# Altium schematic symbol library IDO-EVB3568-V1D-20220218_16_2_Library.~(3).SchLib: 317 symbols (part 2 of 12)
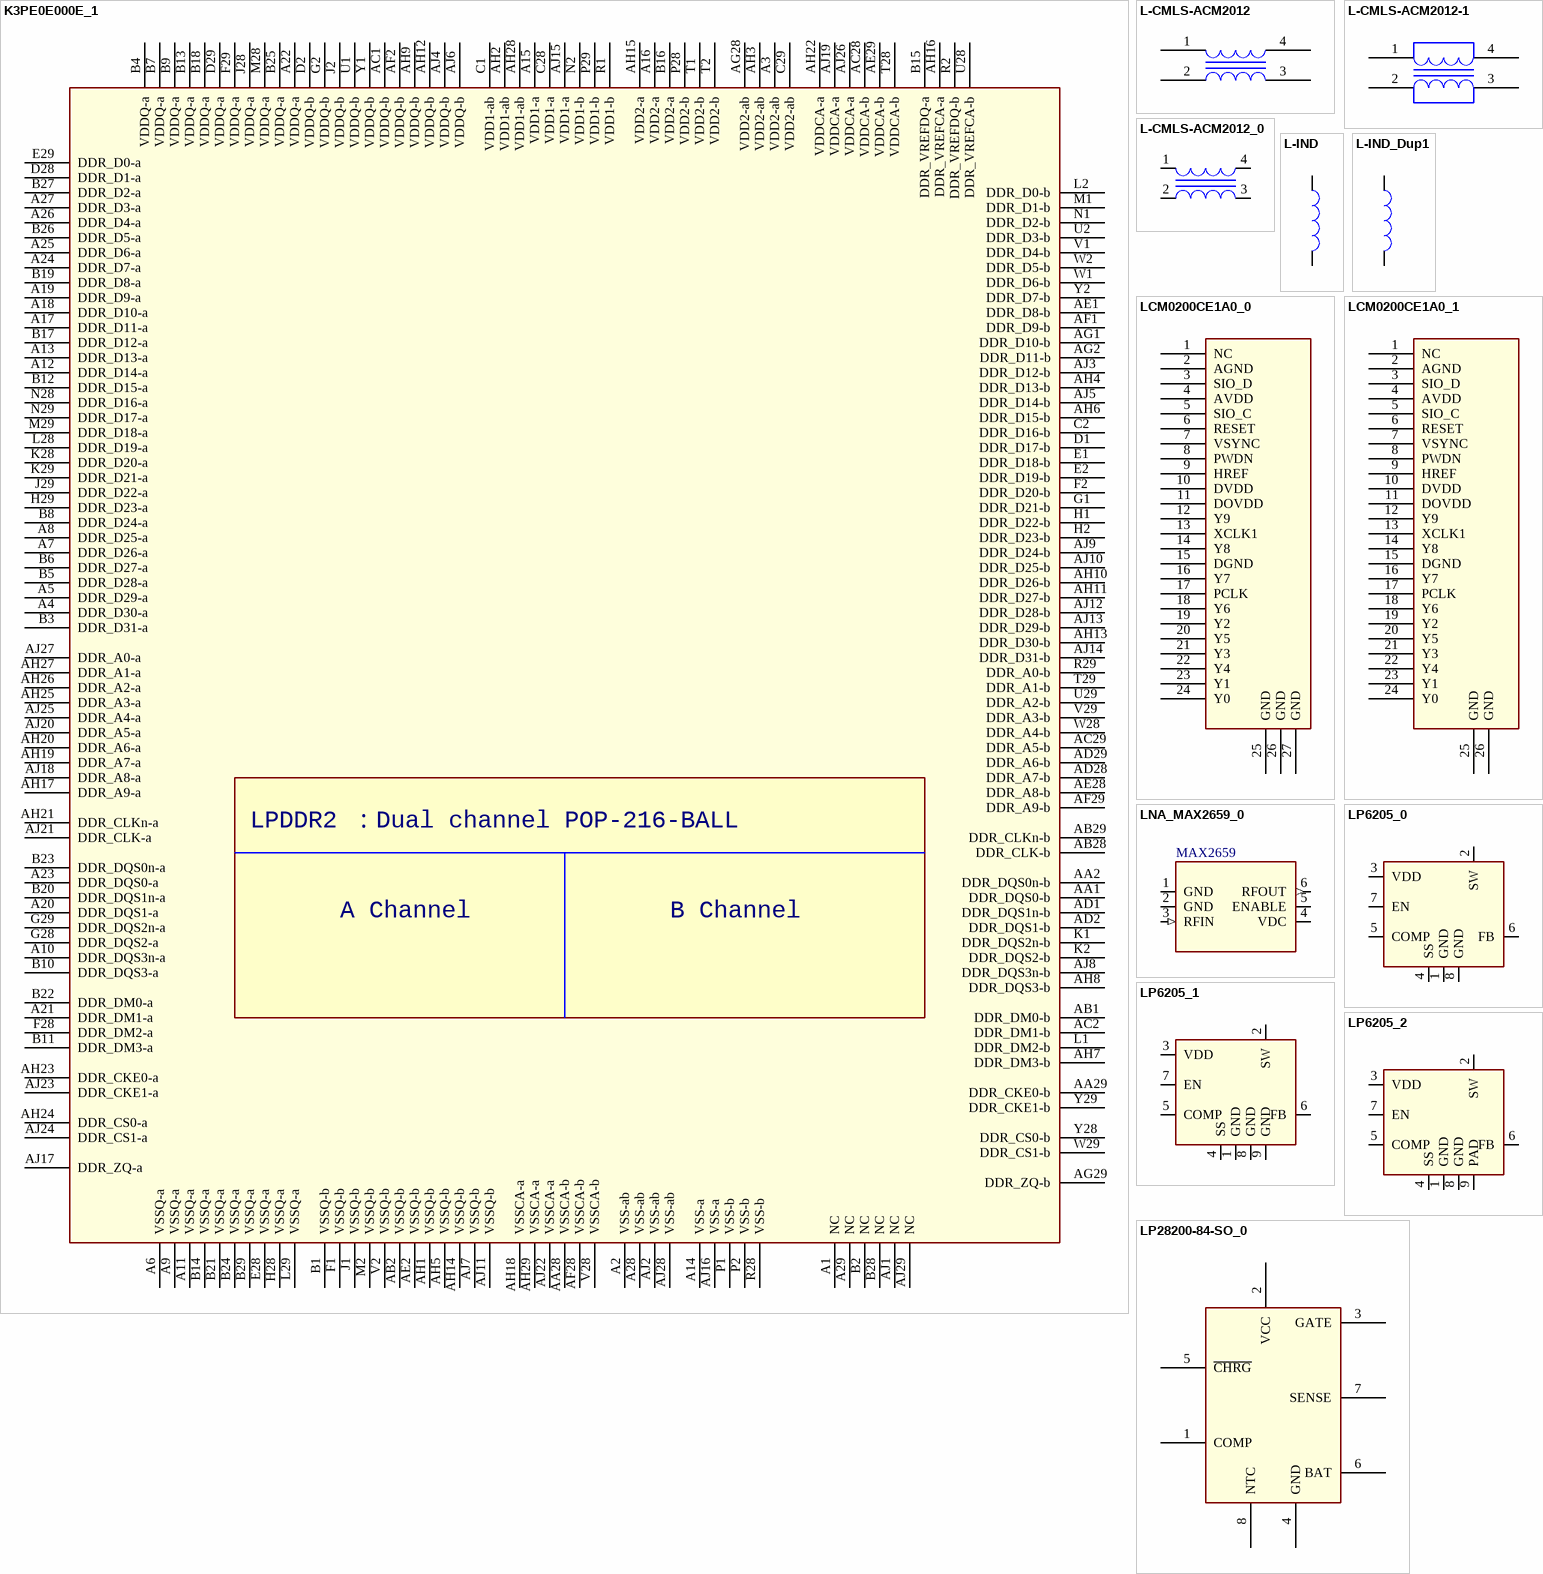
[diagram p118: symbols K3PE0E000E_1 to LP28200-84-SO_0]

## LP6205_1
designator U?
Altium-Right: 80; Altium-Bottom: 70
pins: 1 GND, 2 SW, 3 VDD, 4 SS, 5 COMP, 6 FB, 7 EN, 8 GND, 9 GND

## LP6205_2
designator U?
Altium-Right: 80; Altium-Bottom: 70
pins: 1 GND, 2 SW, 3 VDD, 4 SS, 5 COMP, 6 FB, 7 EN, 8 GND, 9 PAD

## LP28200-84-SO_0
designator U?
Altium-Right: 90; Altium-Bottom: 130
footprint SOP8
pins: 1 COMP, 2 VCC, 3 GATE, 4 GND, 5 ~{CHRG}, 6 BAT, 7 SENSE, 8 NTC

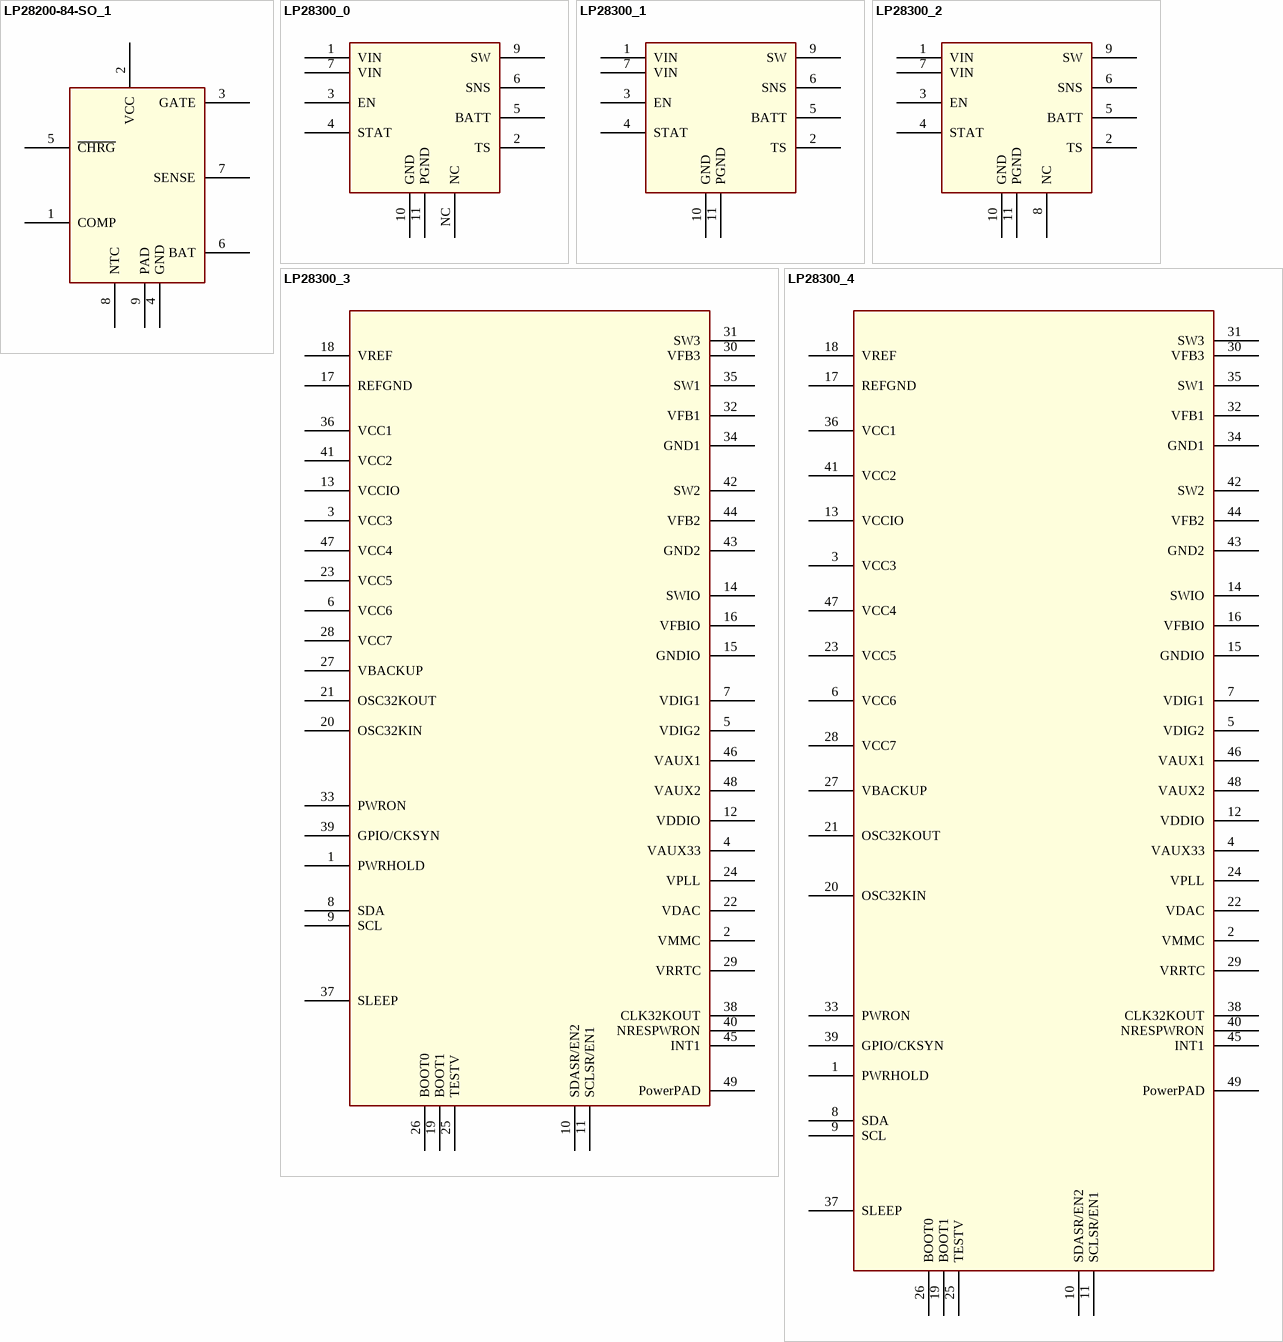
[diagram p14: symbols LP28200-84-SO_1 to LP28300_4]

## LP28200-84-SO_1
designator U?
Altium-Right: 90; Altium-Bottom: 130
footprint SOP8
pins: 1 COMP, 2 VCC, 3 GATE, 4 GND, 5 ~{CHRG}, 6 BAT, 7 SENSE, 8 NTC, 9 PAD

## LP28300_0
designator U?
Altium-Right: 100
footprint TDFN10
pins: 1 VIN, 2 TS, 3 EN, 4 STAT, 5 BATT, 6 SNS, 7 VIN, 9 SW, 10 GND, 11 PGND, NC

## LP28300_1
designator U?
Altium-Right: 100
footprint TDFN10
pins: 1 VIN, 2 TS, 3 EN, 4 STAT, 5 BATT, 6 SNS, 7 VIN, 9 SW, 10 GND, 11 PGND

## LP28300_2
designator U?
Altium-Right: 100
footprint TDFN10
pins: 1 VIN, 2 TS, 3 EN, 4 STAT, 5 BATT, 6 SNS, 7 VIN, 8 NC, 9 SW, 10 GND, 11 PGND

## LP28300_3
designator U?
Altium-Right: 240; Altium-Bottom: 530
footprint TDFN10
pins: 1 PWRHOLD, 2 VMMC, 3 VCC3, 4 VAUX33, 5 VDIG2, 6 VCC6, 7 VDIG1, 8 SDA, 9 SCL, 10 SDASR/EN2, 11 SCLSR/EN1, 12 VDDIO, 13 VCCIO, 14 SWIO, 15 GNDIO, 16 VFBIO, 17 REFGND, 18 VREF, 19 BOOT1, 20 OSC32KIN, 21 OSC32KOUT, 22 VDAC, 23 VCC5, 24 VPLL, 25 TESTV, 26 BOOT0, 27 VBACKUP, 28 VCC7, 29 VRRTC, 30 VFB3, 31 SW3, 32 VFB1, 33 PWRON, 34 GND1, 35 SW1, 36 VCC1, 37 SLEEP, 38 CLK32KOUT, 39 GPIO/CKSYN, 40 NRESPWRON, 41 VCC2, 42 SW2, 43 GND2, 44 VFB2, 45 INT1, 46 VAUX1, 47 VCC4, 48 VAUX2, 49 PowerPAD

## LP28300_4
designator U?
Altium-Right: 240; Altium-Bottom: 640
footprint TDFN10
pins: 1 PWRHOLD, 2 VMMC, 3 VCC3, 4 VAUX33, 5 VDIG2, 6 VCC6, 7 VDIG1, 8 SDA, 9 SCL, 10 SDASR/EN2, 11 SCLSR/EN1, 12 VDDIO, 13 VCCIO, 14 SWIO, 15 GNDIO, 16 VFBIO, 17 REFGND, 18 VREF, 19 BOOT1, 20 OSC32KIN, 21 OSC32KOUT, 22 VDAC, 23 VCC5, 24 VPLL, 25 TESTV, 26 BOOT0, 27 VBACKUP, 28 VCC7, 29 VRRTC, 30 VFB3, 31 SW3, 32 VFB1, 33 PWRON, 34 GND1, 35 SW1, 36 VCC1, 37 SLEEP, 38 CLK32KOUT, 39 GPIO/CKSYN, 40 NRESPWRON, 41 VCC2, 42 SW2, 43 GND2, 44 VFB2, 45 INT1, 46 VAUX1, 47 VCC4, 48 VAUX2, 49 PowerPAD

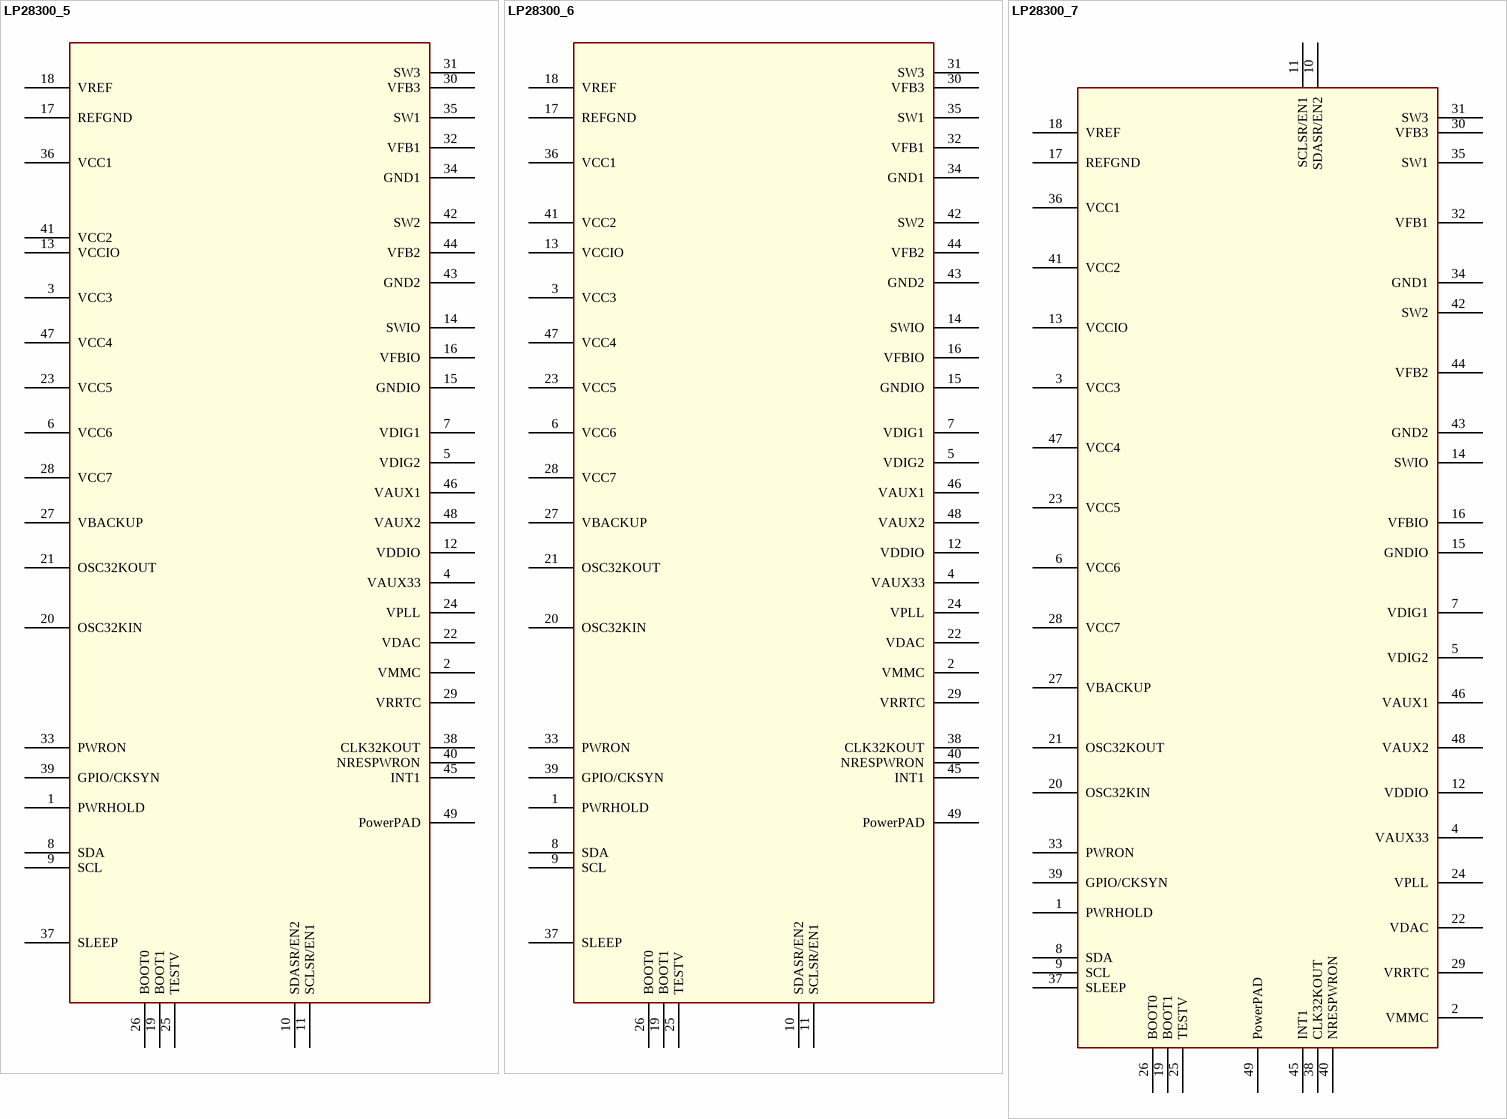
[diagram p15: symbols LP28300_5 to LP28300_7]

## LP28300_5
designator U?
Altium-Right: 240; Altium-Bottom: 640
footprint TDFN10
pins: 1 PWRHOLD, 2 VMMC, 3 VCC3, 4 VAUX33, 5 VDIG2, 6 VCC6, 7 VDIG1, 8 SDA, 9 SCL, 10 SDASR/EN2, 11 SCLSR/EN1, 12 VDDIO, 13 VCCIO, 14 SWIO, 15 GNDIO, 16 VFBIO, 17 REFGND, 18 VREF, 19 BOOT1, 20 OSC32KIN, 21 OSC32KOUT, 22 VDAC, 23 VCC5, 24 VPLL, 25 TESTV, 26 BOOT0, 27 VBACKUP, 28 VCC7, 29 VRRTC, 30 VFB3, 31 SW3, 32 VFB1, 33 PWRON, 34 GND1, 35 SW1, 36 VCC1, 37 SLEEP, 38 CLK32KOUT, 39 GPIO/CKSYN, 40 NRESPWRON, 41 VCC2, 42 SW2, 43 GND2, 44 VFB2, 45 INT1, 46 VAUX1, 47 VCC4, 48 VAUX2, 49 PowerPAD

## LP28300_6
designator U?
Altium-Right: 240; Altium-Bottom: 640
footprint TDFN10
pins: 1 PWRHOLD, 2 VMMC, 3 VCC3, 4 VAUX33, 5 VDIG2, 6 VCC6, 7 VDIG1, 8 SDA, 9 SCL, 10 SDASR/EN2, 11 SCLSR/EN1, 12 VDDIO, 13 VCCIO, 14 SWIO, 15 GNDIO, 16 VFBIO, 17 REFGND, 18 VREF, 19 BOOT1, 20 OSC32KIN, 21 OSC32KOUT, 22 VDAC, 23 VCC5, 24 VPLL, 25 TESTV, 26 BOOT0, 27 VBACKUP, 28 VCC7, 29 VRRTC, 30 VFB3, 31 SW3, 32 VFB1, 33 PWRON, 34 GND1, 35 SW1, 36 VCC1, 37 SLEEP, 38 CLK32KOUT, 39 GPIO/CKSYN, 40 NRESPWRON, 41 VCC2, 42 SW2, 43 GND2, 44 VFB2, 45 INT1, 46 VAUX1, 47 VCC4, 48 VAUX2, 49 PowerPAD

## LP28300_7
designator U?
Altium-Right: 240; Altium-Bottom: 640
footprint TDFN10
pins: 1 PWRHOLD, 2 VMMC, 3 VCC3, 4 VAUX33, 5 VDIG2, 6 VCC6, 7 VDIG1, 8 SDA, 9 SCL, 10 SDASR/EN2, 11 SCLSR/EN1, 12 VDDIO, 13 VCCIO, 14 SWIO, 15 GNDIO, 16 VFBIO, 17 REFGND, 18 VREF, 19 BOOT1, 20 OSC32KIN, 21 OSC32KOUT, 22 VDAC, 23 VCC5, 24 VPLL, 25 TESTV, 26 BOOT0, 27 VBACKUP, 28 VCC7, 29 VRRTC, 30 VFB3, 31 SW3, 32 VFB1, 33 PWRON, 34 GND1, 35 SW1, 36 VCC1, 37 SLEEP, 38 CLK32KOUT, 39 GPIO/CKSYN, 40 NRESPWRON, 41 VCC2, 42 SW2, 43 GND2, 44 VFB2, 45 INT1, 46 VAUX1, 47 VCC4, 48 VAUX2, 49 PowerPAD

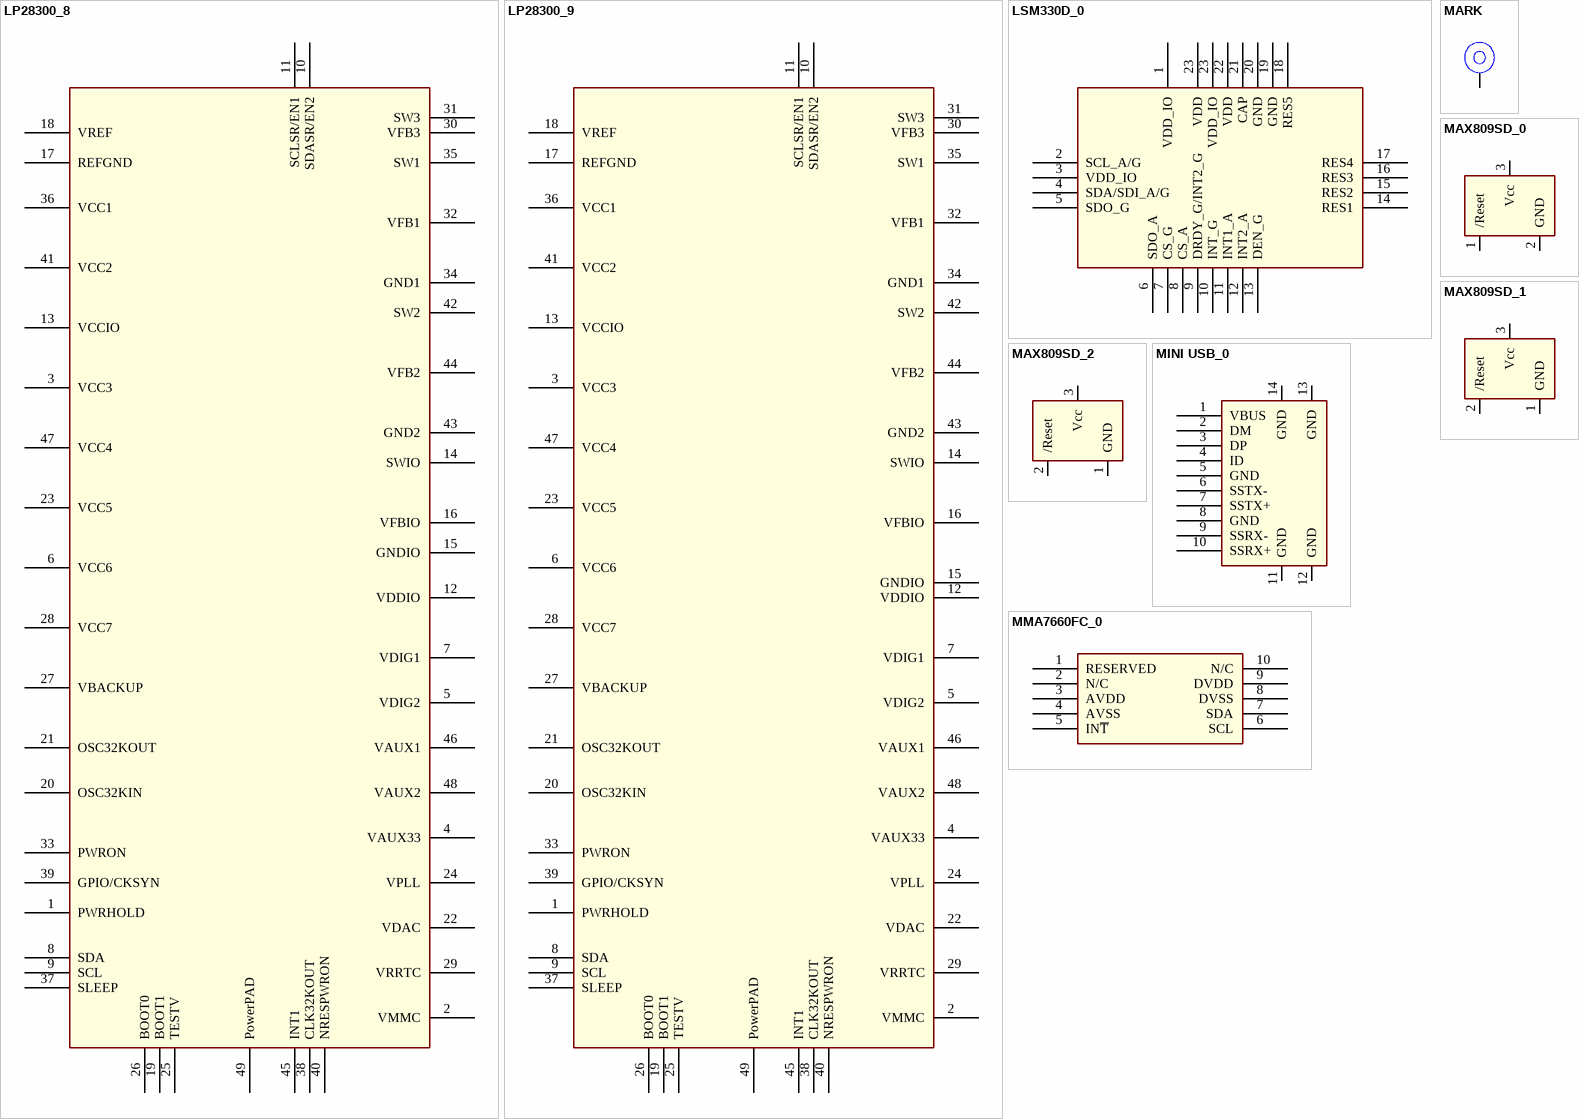
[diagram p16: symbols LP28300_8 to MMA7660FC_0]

## LP28300_8
designator U?
Altium-Right: 240; Altium-Bottom: 640
footprint TDFN10
pins: 1 PWRHOLD, 2 VMMC, 3 VCC3, 4 VAUX33, 5 VDIG2, 6 VCC6, 7 VDIG1, 8 SDA, 9 SCL, 10 SDASR/EN2, 11 SCLSR/EN1, 12 VDDIO, 13 VCCIO, 14 SWIO, 15 GNDIO, 16 VFBIO, 17 REFGND, 18 VREF, 19 BOOT1, 20 OSC32KIN, 21 OSC32KOUT, 22 VDAC, 23 VCC5, 24 VPLL, 25 TESTV, 26 BOOT0, 27 VBACKUP, 28 VCC7, 29 VRRTC, 30 VFB3, 31 SW3, 32 VFB1, 33 PWRON, 34 GND1, 35 SW1, 36 VCC1, 37 SLEEP, 38 CLK32KOUT, 39 GPIO/CKSYN, 40 NRESPWRON, 41 VCC2, 42 SW2, 43 GND2, 44 VFB2, 45 INT1, 46 VAUX1, 47 VCC4, 48 VAUX2, 49 PowerPAD

## LP28300_9
designator U?
Altium-Right: 240; Altium-Bottom: 640
footprint TDFN10
pins: 1 PWRHOLD, 2 VMMC, 3 VCC3, 4 VAUX33, 5 VDIG2, 6 VCC6, 7 VDIG1, 8 SDA, 9 SCL, 10 SDASR/EN2, 11 SCLSR/EN1, 12 VDDIO, 13 VCCIO, 14 SWIO, 15 GNDIO, 16 VFBIO, 17 REFGND, 18 VREF, 19 BOOT1, 20 OSC32KIN, 21 OSC32KOUT, 22 VDAC, 23 VCC5, 24 VPLL, 25 TESTV, 26 BOOT0, 27 VBACKUP, 28 VCC7, 29 VRRTC, 30 VFB3, 31 SW3, 32 VFB1, 33 PWRON, 34 GND1, 35 SW1, 36 VCC1, 37 SLEEP, 38 CLK32KOUT, 39 GPIO/CKSYN, 40 NRESPWRON, 41 VCC2, 42 SW2, 43 GND2, 44 VFB2, 45 INT1, 46 VAUX1, 47 VCC4, 48 VAUX2, 49 PowerPAD

## LSM330D_0
designator U?
Altium-Right: 190; Altium-Bottom: 120
footprint L3G4200D
pins: 1 VDD_IO, 2 SCL_A/G, 3 VDD_IO, 4 SDA/SDI_A/G, 5 SDO_G, 6 SDO_A, 7 CS_G, 8 CS_A, 9 DRDY_G/INT2_G, 10 INT_G, 11 INT1_A, 12 INT2_A, 13 DEN_G, 14 RES1, 15 RES2, 16 RES3, 17 RES4, 18 RES5, 19 GND (power), 20 GND (power), 21 CAP, 22 VDD, 23 VDD, 23 VDD_IO

## MARK
designator M?
Altium-Right: 20
pins: 1

## MAX809SD_0
designator U?
Altium-Right: 60; Altium-Bottom: 40
pins: 1 /Reset, 2 GND, 3 Vcc

## MAX809SD_1
designator U?
Altium-Right: 60; Altium-Bottom: 40
pins: 1 GND, 2 /Reset, 3 Vcc

## MAX809SD_2
designator U?
Altium-Right: 60; Altium-Bottom: 40
pins: 1 GND, 2 /Reset, 3 Vcc

## MINI USB_0
designator U?
Altium-Right: 70; Altium-Bottom: 110
pins: 1 VBUS, 2 DM, 3 DP, 4 ID, 5 GND, 6 SSTX-, 7 SSTX+, 8 GND (power), 9 SSRX-, 10 SSRX+, 11 GND, 12 GND, 13 GND, 14 GND

## MMA7660FC_0
designator U?
Altium-Right: 110; Altium-Bottom: 60
pins: 1 RESERVED, 2 N/C, 3 AVDD, 4 AVSS, 5 IN~{T}, 6 SCL, 7 SDA, 8 DVSS, 9 DVDD, 10 N/C

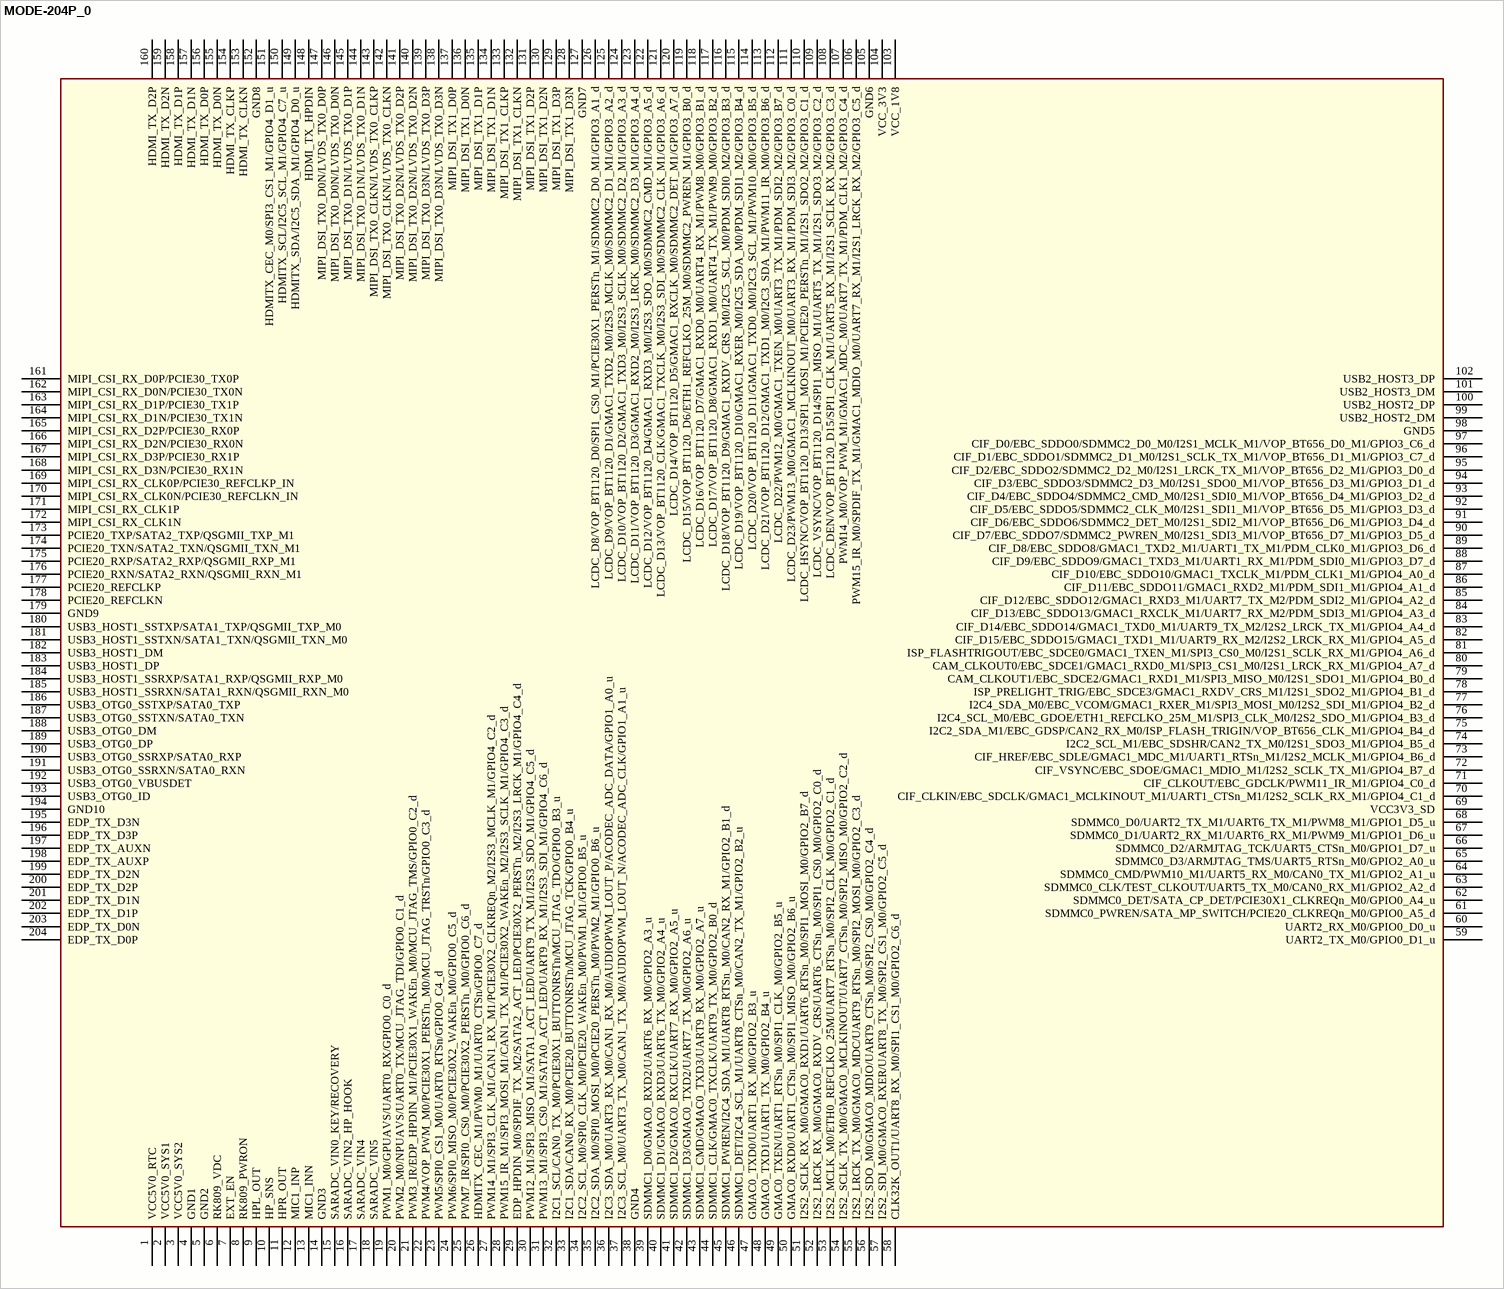
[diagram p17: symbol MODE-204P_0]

## MODE-204P_0
designator M?
Altium-Right: 1060; Altium-Bottom: 880
pins: 1 VCC5V0_RTC, 2 VCC5V0_SYS1, 3 VCC5V0_SYS2 (power), 4 GND1, 5 GND2, 6 RK809_VDC, 7 EXT_EN, 8 RK809_PWRON, 9 HPL_OUT, 10 HP_SNS, 11 HPR_OUT, 12 MIC1_INP, 13 MIC1_INN, 14 GND3, 15 SARADC_VIN0_KEY/RECOVERY, 16 SARADC_VIN2_HP_HOOK, 17 SARADC_VIN4, 18 SARADC_VIN5, 19 PWM1_M0/GPUAVS/UART0_RX/GPIO0_C0_d, 20 PWM2_M0/NPUAVS/UART0_TX/MCU_JTAG_TDI/GPIO0_C1_d, 21 PWM3_IR/EDP_HPDIN_M1/PCIE30X1_WAKEn_M0/MCU_JTAG_TMS/GPIO0_C2_d, 22 PWM4/VOP_PWM_M0/PCIE30X1_PERSTn_M0/MCU_JTAG_TRSTn/GPIO0_C3_d, 23 PWM5/SPI0_CS1_M0/UART0_RTSn/GPIO0_C4_d, 24 PWM6/SPI0_MISO_M0/PCIE30X2_WAKEn_M0/GPIO0_C5_d, 25 PWM7_IR/SPI0_CS0_M0/PCIE30X2_PERSTn_M0/GPIO0_C6_d, 26 HDMITX_CEC_M1/PWM0_M1/UART0_CTSn/GPIO0_C7_d (power), 27 PWM14_M1/SPI3_CLK_M1/CAN1_RX_M1/PCIE30X2_CLKREQn_M2/I2S3_MCLK_M1/GPIO4_C2_d, 28 PWM15_IR_M1/SPI3_MOSI_M1/CAN1_TX_M1/PCIE30X2_WAKEn_M2/I2S3_SCLK_M1/GPIO4_C3_d, 29 EDP_HPDIN_M0/SPDIF_TX_M2/SATA2_ACT_LED/PCIE30X2_PERSTn_M2/I2S3_LRCK_M1/GPIO4_C4_d, 30 PWM12_M1/SPI3_MISO_M1/SATA1_ACT_LED/UART9_TX_M1/I2S3_SDO_M1/GPIO4_C5_d, 31 PWM13_M1/SPI3_CS0_M1/SATA0_ACT_LED/UART9_RX_M1/I2S3_SDI_M1/GPIO4_C6_d, 32 I2C1_SCL/CAN0_TX_M0/PCIE30X1_BUTTONRSTn/MCU_JTAG_TDO/GPIO0_B3_u, 33 I2C1_SDA/CAN0_RX_M0/PCIE20_BUTTONRSTn/MCU_JTAG_TCK/GPIO0_B4_u, 34 I2C2_SCL_M0/SPI0_CLK_M0/PCIE20_WAKEn_M0/PWM1_M1/GPIO0_B5_u, 35 I2C2_SDA_M0/SPI0_MOSI_M0/PCIE20_PERSTn_M0/PWM2_M1/GPIO0_B6_u, 36 I2C3_SDA_M0/UART3_RX_M0/CAN1_RX_M0/AUDIOPWM_LOUT_P/ACODEC_ADC_DATA/GPIO1_A0_u, 37 I2C3_SCL_M0/UART3_TX_M0/CAN1_TX_M0/AUDIOPWM_LOUT_N/ACODEC_ADC_CLK/GPIO1_A1_u, 38 GND4, 39 SDMMC1_D0/GMAC0_RXD2/UART6_RX_M0/GPIO2_A3_u, 40 SDMMC1_D1/GMAC0_RXD3/UART6_TX_M0/GPIO2_A4_u, 41 SDMMC1_D2/GMAC0_RXCLK/UART7_RX_M0/GPIO2_A5_u, 42 SDMMC1_D3/GMAC0_TXD2/UART7_TX_M0/GPIO2_A6_u, 43 SDMMC1_CMD/GMAC0_TXD3/UART9_RX_M0/GPIO2_A7_u, 44 SDMMC1_CLK/GMAC0_TXCLK/UART9_TX_M0/GPIO2_B0_d, 45 SDMMC1_PWREN/I2C4_SDA_M1/UART8_RTSn_M0/CAN2_RX_M1/GPIO2_B1_d, 46 SDMMC1_DET/I2C4_SCL_M1/UART8_CTSn_M0/CAN2_TX_M1/GPIO2_B2_u, 47 GMAC0_TXD0/UART1_RX_M0/GPIO2_B3_u, 48 GMAC0_TXD1/UART1_TX_M0/GPIO2_B4_u (power), 49 GMAC0_TXEN/UART1_RTSn_M0/SPI1_CLK_M0/GPIO2_B5_u (power), 50 GMAC0_RXD0/UART1_CTSn_M0/SPI1_MISO_M0/GPIO2_B6_u, 51 I2S2_SCLK_RX_M0/GMAC0_RXD1/UART6_RTSn_M0/SPI1_MOSI_M0/GPIO2_B7_d, 52 I2S2_LRCK_RX_M0/GMAC0_RXDV_CRS/UART6_CTSn_M0/SPI1_CS0_M0/GPIO2_C0_d, 53 I2S2_MCLK_M0/ETH0_REFCLKO_25M/UART7_RTSn_M0/SPI2_CLK_M0/GPIO2_C1_d, 54 I2S2_SCLK_TX_M0/GMAC0_MCLKINOUT/UART7_CTSn_M0/SPI2_MISO_M0/GPIO2_C2_d, 55 I2S2_LRCK_TX_M0/GMAC0_MDC/UART9_RTSn_M0/SPI2_MOSI_M0/GPIO2_C3_d, 56 I2S2_SDO_M0/GMAC0_MDIO/UART9_CTSn_M0/SPI2_CS0_M0/GPIO2_C4_d, 57 I2S2_SDI_M0/GMAC0_RXER/UART8_TX_M0/SPI2_CS1_M0/GPIO2_C5_d, 58 CLK32K_OUT1/UART8_RX_M0/SPI1_CS1_M0/GPIO2_C6_d, 59 UART2_TX_M0/GPIO0_D1_u, 60 UART2_RX_M0/GPIO0_D0_u, 61 SDMMC0_PWREN/SATA_MP_SWITCH/PCIE20_CLKREQn_M0/GPIO0_A5_d, 62 SDMMC0_DET/SATA_CP_DET/PCIE30X1_CLKREQn_M0/GPIO0_A4_u, 63 SDMMC0_CLK/TEST_CLKOUT/UART5_TX_M0/CAN0_RX_M1/GPIO2_A2_d, 64 SDMMC0_CMD/PWM10_M1/UART5_RX_M0/CAN0_TX_M1/GPIO2_A1_u (power), 65 SDMMC0_D3/ARMJTAG_TMS/UART5_RTSn_M0/GPIO2_A0_u, 66 SDMMC0_D2/ARMJTAG_TCK/UART5_CTSn_M0/GPIO1_D7_u, 67 SDMMC0_D1/UART2_RX_M1/UART6_RX_M1/PWM9_M1/GPIO1_D6_u, 68 SDMMC0_D0/UART2_TX_M1/UART6_TX_M1/PWM8_M1/GPIO1_D5_u, 69 VCC3V3_SD, 70 CIF_CLKIN/EBC_SDCLK/GMAC1_MCLKINOUT_M1/UART1_CTSn_M1/I2S2_SCLK_RX_M1/GPIO4_C1_d, 71 CIF_CLKOUT/EBC_GDCLK/PWM11_IR_M1/GPIO4_C0_d, 72 CIF_VSYNC/EBC_SDOE/GMAC1_MDIO_M1/I2S2_SCLK_TX_M1/GPIO4_B7_d, 73 CIF_HREF/EBC_SDLE/GMAC1_MDC_M1/UART1_RTSn_M1/I2S2_MCLK_M1/GPIO4_B6_d, 74 I2C2_SCL_M1/EBC_SDSHR/CAN2_TX_M0/I2S1_SDO3_M1/GPIO4_B5_d, 75 I2C2_SDA_M1/EBC_GDSP/CAN2_RX_M0/ISP_FLASH_TRIGIN/VOP_BT656_CLK_M1/GPIO4_B4_d, 76 I2C4_SCL_M0/EBC_GDOE/ETH1_REFCLKO_25M_M1/SPI3_CLK_M0/I2S2_SDO_M1/GPIO4_B3_d, 77 I2C4_SDA_M0/EBC_VCOM/GMAC1_RXER_M1/SPI3_MOSI_M0/I2S2_SDI_M1/GPIO4_B2_d, 78 ISP_PRELIGHT_TRIG/EBC_SDCE3/GMAC1_RXDV_CRS_M1/I2S1_SDO2_M1/GPIO4_B1_d (power), 79 CAM_CLKOUT1/EBC_SDCE2/GMAC1_RXD1_M1/SPI3_MISO_M0/I2S1_SDO1_M1/GPIO4_B0_d, 80 CAM_CLKOUT0/EBC_SDCE1/GMAC1_RXD0_M1/SPI3_CS1_M0/I2S1_LRCK_RX_M1/GPIO4_A7_d, 81 ISP_FLASHTRIGOUT/EBC_SDCE0/GMAC1_TXEN_M1/SPI3_CS0_M0/I2S1_SCLK_RX_M1/GPIO4_A6_d, 82 CIF_D15/EBC_SDDO15/GMAC1_TXD1_M1/UART9_RX_M2/I2S2_LRCK_RX_M1/GPIO4_A5_d, 83 CIF_D14/EBC_SDDO14/GMAC1_TXD0_M1/UART9_TX_M2/I2S2_LRCK_TX_M1/GPIO4_A4_d, 84 CIF_D13/EBC_SDDO13/GMAC1_RXCLK_M1/UART7_RX_M2/PDM_SDI3_M1/GPIO4_A3_d, 85 CIF_D12/EBC_SDDO12/GMAC1_RXD3_M1/UART7_TX_M2/PDM_SDI2_M1/GPIO4_A2_d, 86 CIF_D11/EBC_SDDO11/GMAC1_RXD2_M1/PDM_SDI1_M1/GPIO4_A1_d, 87 CIF_D10/EBC_SDDO10/GMAC1_TXCLK_M1/PDM_CLK1_M1/GPIO4_A0_d, 88 CIF_D9/EBC_SDDO9/GMAC1_TXD3_M1/UART1_RX_M1/PDM_SDI0_M1/GPIO3_D7_d, 89 CIF_D8/EBC_SDDO8/GMAC1_TXD2_M1/UART1_TX_M1/PDM_CLK0_M1/GPIO3_D6_d, 90 CIF_D7/EBC_SDDO7/SDMMC2_PWREN_M0/I2S1_SDI3_M1/VOP_BT656_D7_M1/GPIO3_D5_d, 91 CIF_D6/EBC_SDDO6/SDMMC2_DET_M0/I2S1_SDI2_M1/VOP_BT656_D6_M1/GPIO3_D4_d, 92 CIF_D5/EBC_SDDO5/SDMMC2_CLK_M0/I2S1_SDI1_M1/VOP_BT656_D5_M1/GPIO3_D3_d, 93 CIF_D4/EBC_SDDO4/SDMMC2_CMD_M0/I2S1_SDI0_M1/VOP_BT656_D4_M1/GPIO3_D2_d, 94 CIF_D3/EBC_SDDO3/SDMMC2_D3_M0/I2S1_SDO0_M1/VOP_BT656_D3_M1/GPIO3_D1_d, 95 CIF_D2/EBC_SDDO2/SDMMC2_D2_M0/I2S1_LRCK_TX_M1/VOP_BT656_D2_M1/GPIO3_D0_d, 96 CIF_D1/EBC_SDDO1/SDMMC2_D1_M0/I2S1_SCLK_TX_M1/VOP_BT656_D1_M1/GPIO3_C7_d, 97 CIF_D0/EBC_SDDO0/SDMMC2_D0_M0/I2S1_MCLK_M1/VOP_BT656_D0_M1/GPIO3_C6_d, 98 GND5, 99 USB2_HOST2_DM, 100 USB2_HOST2_DP, 101 USB2_HOST3_DM (power), 102 USB2_HOST3_DP, 103 VCC_1V8, 104 VCC_3V3, 105 GND6, 106 PWM15_IR_M0/SPDIF_TX_M1/GMAC1_MDIO_M0/UART7_RX_M1/I2S1_LRCK_RX_M2/GPIO3_C5_d, 107 PWM14_M0/VOP_PWM_M1/GMAC1_MDC_M0/UART7_TX_M1/PDM_CLK1_M2/GPIO3_C4_d, 108 LCDC_DEN/VOP_BT1120_D15/SPI1_CLK_M1/UART5_RX_M1/I2S1_SCLK_RX_M2/GPIO3_C3_d, 109 LCDC_VSYNC/VOP_BT1120_D14/SPI1_MISO_M1/UART5_TX_M1/I2S1_SDO3_M2/GPIO3_C2_d, 110 LCDC_HSYNC/VOP_BT1120_D13/SPI1_MOSI_M1/PCIE20_PERSTn_M1/I2S1_SDO2_M2/GPIO3_C1_d, 111 LCDC_D23/PWM13_M0/GMAC1_MCLKINOUT_M0/UART3_RX_M1/PDM_SDI3_M2/GPIO3_C0_d, 112 LCDC_D22/PWM12_M0/GMAC1_TXEN_M0/UART3_TX_M1/PDM_SDI2_M2/GPIO3_B7_d, 113 LCDC_D21/VOP_BT1120_D12/GMAC1_TXD1_M0/I2C3_SDA_M1/PWM11_IR_M0/GPIO3_B6_d, 114 LCDC_D20/VOP_BT1120_D11/GMAC1_TXD0_M0/I2C3_SCL_M1/PWM10_M0/GPIO3_B5_d, 115 LCDC_D19/VOP_BT1120_D10/GMAC1_RXER_M0/I2C5_SDA_M0/PDM_SDI1_M2/GPIO3_B4_d, 116 LCDC_D18/VOP_BT1120_D9/GMAC1_RXDV_CRS_M0/I2C5_SCL_M0/PDM_SDI0_M2/GPIO3_B3_d, 117 LCDC_D17/VOP_BT1120_D8/GMAC1_RXD1_M0/UART4_TX_M1/PWM9_M0/GPIO3_B2_d, 118 LCDC_D16/VOP_BT1120_D7/GMAC1_RXD0_M0/UART4_RX_M1/PWM8_M0/GPIO3_B1_d, 119 LCDC_D15/VOP_BT1120_D6/ETH1_REFCLKO_25M_M0/SDMMC2_PWREN_M1/GPIO3_B0_d, 120 LCDC_D14/VOP_BT1120_D5/GMAC1_RXCLK_M0/SDMMC2_DET_M1/GPIO3_A7_d, 121 LCDC_D13/VOP_BT1120_CLK/GMAC1_TXCLK_M0/I2S3_SDI_M0/SDMMC2_CLK_M1/GPIO3_A6_d, 122 LCDC_D12/VOP_BT1120_D4/GMAC1_RXD3_M0/I2S3_SDO_M0/SDMMC2_CMD_M1/GPIO3_A5_d (power), 123 LCDC_D11/VOP_BT1120_D3/GMAC1_RXD2_M0/I2S3_LRCK_M0/SDMMC2_D3_M1/GPIO3_A4_d, 124 LCDC_D10/VOP_BT1120_D2/GMAC1_TXD3_M0/I2S3_SCLK_M0/SDMMC2_D2_M1/GPIO3_A3_d, 125 LCDC_D9/VOP_BT1120_D1/GMAC1_TXD2_M0/I2S3_MCLK_M0/SDMMC2_D1_M1/GPIO3_A2_d, 126 LCDC_D8/VOP_BT1120_D0/SPI1_CS0_M1/PCIE30X1_PERSTn_M1/SDMMC2_D0_M1/GPIO3_A1_d, 127 GND7, 128 MIPI_DSI_TX1_D3N, 129 MIPI_DSI_TX1_D3P, 130 MIPI_DSI_TX1_D2N (power), 131 MIPI_DSI_TX1_D2P, 132 MIPI_DSI_TX1_CLKN, 133 MIPI_DSI_TX1_CLKP, 134 MIPI_DSI_TX1_D1N, 135 MIPI_DSI_TX1_D1P, 136 MIPI_DSI_TX1_D0N, 137 MIPI_DSI_TX1_D0P, 138 MIPI_DSI_TX0_D3N/LVDS_TX0_D3N, 139 MIPI_DSI_TX0_D3N/LVDS_TX0_D3P, 140 MIPI_DSI_TX0_D2N/LVDS_TX0_D2N, 141 MIPI_DSI_TX0_D2N/LVDS_TX0_D2P (power), 142 MIPI_DSI_TX0_CLKN/LVDS_TX0_CLKN (power), 143 MIPI_DSI_TX0_CLKN/LVDS_TX0_CLKP, 144 MIPI_DSI_TX0_D1N/LVDS_TX0_D1N, 145 MIPI_DSI_TX0_D1N/LVDS_TX0_D1P (power), 146 MIPI_DSI_TX0_D0N/LVDS_TX0_D0N (power), 147 MIPI_DSI_TX0_D0N/LVDS_TX0_D0P (power), 148 HDMI_TX_HPDIN (power), 149 HDMITX_SDA/I2C5_SDA_M1/GPIO4_D0_u, 150 HDMITX_SCL/I2C5_SCL_M1/GPIO4_C7_u, 151 HDMITX_CEC_M0/SPI3_CS1_M1/GPIO4_D1_u, 152 GND8, 153 HDMI_TX_CLKN, 154 HDMI_TX_CLKP, 155 HDMI_TX_D0N, 156 HDMI_TX_D0P, 157 HDMI_TX_D1N, 158 HDMI_TX_D1P, 159 HDMI_TX_D2N, 160 HDMI_TX_D2P (power), 161 MIPI_CSI_RX_D0P/PCIE30_TX0P, 162 MIPI_CSI_RX_D0N/PCIE30_TX0N, 163 MIPI_CSI_RX_D1P/PCIE30_TX1P, 164 MIPI_CSI_RX_D1N/PCIE30_TX1N, 165 MIPI_CSI_RX_D2P/PCIE30_RX0P, 166 MIPI_CSI_RX_D2N/PCIE30_RX0N, 167 MIPI_CSI_RX_D3P/PCIE30_RX1P, 168 MIPI_CSI_RX_D3N/PCIE30_RX1N, 169 MIPI_CSI_RX_CLK0P/PCIE30_REFCLKP_IN, 170 MIPI_CSI_RX_CLK0N/PCIE30_REFCLKN_IN, 171 MIPI_CSI_RX_CLK1P, 172 MIPI_CSI_RX_CLK1N, 173 PCIE20_TXP/SATA2_TXP/QSGMII_TXP_M1, 174 PCIE20_TXN/SATA2_TXN/QSGMII_TXN_M1, 175 PCIE20_RXP/SATA2_RXP/QSGMII_RXP_M1, 176 PCIE20_RXN/SATA2_RXN/QSGMII_RXN_M1, 177 PCIE20_REFCLKP, 178 PCIE20_REFCLKN, 179 GND9, 180 USB3_HOST1_SSTXP/SATA1_TXP/QSGMII_TXP_M0, 181 USB3_HOST1_SSTXN/SATA1_TXN/QSGMII_TXN_M0, 182 USB3_HOST1_DM, 183 USB3_HOST1_DP, 184 USB3_HOST1_SSRXP/SATA1_RXP/QSGMII_RXP_M0, 185 USB3_HOST1_SSRXN/SATA1_RXN/QSGMII_RXN_M0, 186 USB3_OTG0_SSTXP/SATA0_TXP, 187 USB3_OTG0_SSTXN/SATA0_TXN, 188 USB3_OTG0_DM, 189 USB3_OTG0_DP, 190 USB3_OTG0_SSRXP/SATA0_RXP, 191 USB3_OTG0_SSRXN/SATA0_RXN, 192 USB3_OTG0_VBUSDET, 193 USB3_OTG0_ID, 194 GND10, 195 EDP_TX_D3N, 196 EDP_TX_D3P, 197 EDP_TX_AUXN, 198 EDP_TX_AUXP, 199 EDP_TX_D2N, 200 EDP_TX_D2P, 201 EDP_TX_D1N, 202 EDP_TX_D1P (power), 203 EDP_TX_D0N, 204 EDP_TX_D0P

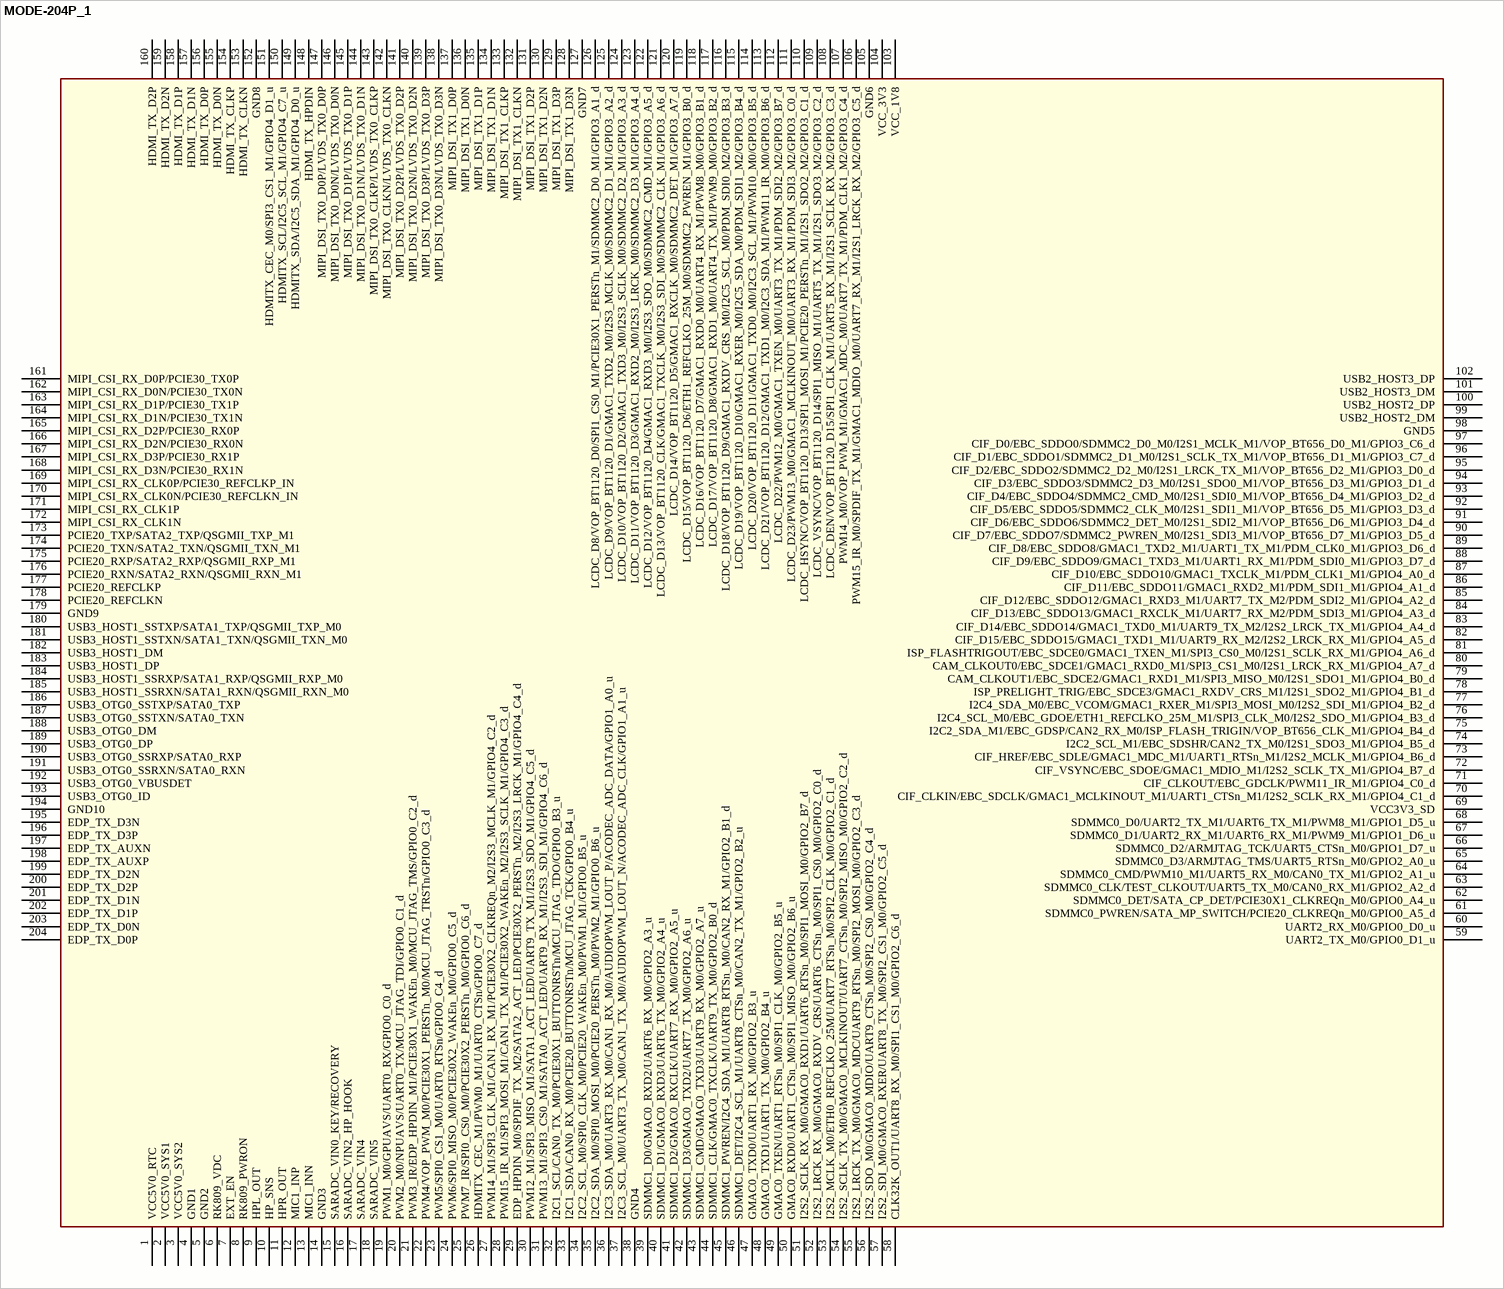
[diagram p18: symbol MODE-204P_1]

## MODE-204P_1
designator M?
Altium-Right: 1060; Altium-Bottom: 880
pins: 1 VCC5V0_RTC, 2 VCC5V0_SYS1, 3 VCC5V0_SYS2 (power), 4 GND1, 5 GND2, 6 RK809_VDC, 7 EXT_EN, 8 RK809_PWRON, 9 HPL_OUT, 10 HP_SNS, 11 HPR_OUT, 12 MIC1_INP, 13 MIC1_INN, 14 GND3, 15 SARADC_VIN0_KEY/RECOVERY, 16 SARADC_VIN2_HP_HOOK, 17 SARADC_VIN4, 18 SARADC_VIN5, 19 PWM1_M0/GPUAVS/UART0_RX/GPIO0_C0_d, 20 PWM2_M0/NPUAVS/UART0_TX/MCU_JTAG_TDI/GPIO0_C1_d, 21 PWM3_IR/EDP_HPDIN_M1/PCIE30X1_WAKEn_M0/MCU_JTAG_TMS/GPIO0_C2_d, 22 PWM4/VOP_PWM_M0/PCIE30X1_PERSTn_M0/MCU_JTAG_TRSTn/GPIO0_C3_d, 23 PWM5/SPI0_CS1_M0/UART0_RTSn/GPIO0_C4_d, 24 PWM6/SPI0_MISO_M0/PCIE30X2_WAKEn_M0/GPIO0_C5_d, 25 PWM7_IR/SPI0_CS0_M0/PCIE30X2_PERSTn_M0/GPIO0_C6_d, 26 HDMITX_CEC_M1/PWM0_M1/UART0_CTSn/GPIO0_C7_d (power), 27 PWM14_M1/SPI3_CLK_M1/CAN1_RX_M1/PCIE30X2_CLKREQn_M2/I2S3_MCLK_M1/GPIO4_C2_d, 28 PWM15_IR_M1/SPI3_MOSI_M1/CAN1_TX_M1/PCIE30X2_WAKEn_M2/I2S3_SCLK_M1/GPIO4_C3_d, 29 EDP_HPDIN_M0/SPDIF_TX_M2/SATA2_ACT_LED/PCIE30X2_PERSTn_M2/I2S3_LRCK_M1/GPIO4_C4_d, 30 PWM12_M1/SPI3_MISO_M1/SATA1_ACT_LED/UART9_TX_M1/I2S3_SDO_M1/GPIO4_C5_d, 31 PWM13_M1/SPI3_CS0_M1/SATA0_ACT_LED/UART9_RX_M1/I2S3_SDI_M1/GPIO4_C6_d, 32 I2C1_SCL/CAN0_TX_M0/PCIE30X1_BUTTONRSTn/MCU_JTAG_TDO/GPIO0_B3_u, 33 I2C1_SDA/CAN0_RX_M0/PCIE20_BUTTONRSTn/MCU_JTAG_TCK/GPIO0_B4_u, 34 I2C2_SCL_M0/SPI0_CLK_M0/PCIE20_WAKEn_M0/PWM1_M1/GPIO0_B5_u, 35 I2C2_SDA_M0/SPI0_MOSI_M0/PCIE20_PERSTn_M0/PWM2_M1/GPIO0_B6_u, 36 I2C3_SDA_M0/UART3_RX_M0/CAN1_RX_M0/AUDIOPWM_LOUT_P/ACODEC_ADC_DATA/GPIO1_A0_u, 37 I2C3_SCL_M0/UART3_TX_M0/CAN1_TX_M0/AUDIOPWM_LOUT_N/ACODEC_ADC_CLK/GPIO1_A1_u, 38 GND4, 39 SDMMC1_D0/GMAC0_RXD2/UART6_RX_M0/GPIO2_A3_u, 40 SDMMC1_D1/GMAC0_RXD3/UART6_TX_M0/GPIO2_A4_u, 41 SDMMC1_D2/GMAC0_RXCLK/UART7_RX_M0/GPIO2_A5_u, 42 SDMMC1_D3/GMAC0_TXD2/UART7_TX_M0/GPIO2_A6_u, 43 SDMMC1_CMD/GMAC0_TXD3/UART9_RX_M0/GPIO2_A7_u, 44 SDMMC1_CLK/GMAC0_TXCLK/UART9_TX_M0/GPIO2_B0_d, 45 SDMMC1_PWREN/I2C4_SDA_M1/UART8_RTSn_M0/CAN2_RX_M1/GPIO2_B1_d, 46 SDMMC1_DET/I2C4_SCL_M1/UART8_CTSn_M0/CAN2_TX_M1/GPIO2_B2_u, 47 GMAC0_TXD0/UART1_RX_M0/GPIO2_B3_u, 48 GMAC0_TXD1/UART1_TX_M0/GPIO2_B4_u (power), 49 GMAC0_TXEN/UART1_RTSn_M0/SPI1_CLK_M0/GPIO2_B5_u (power), 50 GMAC0_RXD0/UART1_CTSn_M0/SPI1_MISO_M0/GPIO2_B6_u, 51 I2S2_SCLK_RX_M0/GMAC0_RXD1/UART6_RTSn_M0/SPI1_MOSI_M0/GPIO2_B7_d, 52 I2S2_LRCK_RX_M0/GMAC0_RXDV_CRS/UART6_CTSn_M0/SPI1_CS0_M0/GPIO2_C0_d, 53 I2S2_MCLK_M0/ETH0_REFCLKO_25M/UART7_RTSn_M0/SPI2_CLK_M0/GPIO2_C1_d, 54 I2S2_SCLK_TX_M0/GMAC0_MCLKINOUT/UART7_CTSn_M0/SPI2_MISO_M0/GPIO2_C2_d, 55 I2S2_LRCK_TX_M0/GMAC0_MDC/UART9_RTSn_M0/SPI2_MOSI_M0/GPIO2_C3_d, 56 I2S2_SDO_M0/GMAC0_MDIO/UART9_CTSn_M0/SPI2_CS0_M0/GPIO2_C4_d, 57 I2S2_SDI_M0/GMAC0_RXER/UART8_TX_M0/SPI2_CS1_M0/GPIO2_C5_d, 58 CLK32K_OUT1/UART8_RX_M0/SPI1_CS1_M0/GPIO2_C6_d, 59 UART2_TX_M0/GPIO0_D1_u, 60 UART2_RX_M0/GPIO0_D0_u, 61 SDMMC0_PWREN/SATA_MP_SWITCH/PCIE20_CLKREQn_M0/GPIO0_A5_d, 62 SDMMC0_DET/SATA_CP_DET/PCIE30X1_CLKREQn_M0/GPIO0_A4_u, 63 SDMMC0_CLK/TEST_CLKOUT/UART5_TX_M0/CAN0_RX_M1/GPIO2_A2_d, 64 SDMMC0_CMD/PWM10_M1/UART5_RX_M0/CAN0_TX_M1/GPIO2_A1_u (power), 65 SDMMC0_D3/ARMJTAG_TMS/UART5_RTSn_M0/GPIO2_A0_u, 66 SDMMC0_D2/ARMJTAG_TCK/UART5_CTSn_M0/GPIO1_D7_u, 67 SDMMC0_D1/UART2_RX_M1/UART6_RX_M1/PWM9_M1/GPIO1_D6_u, 68 SDMMC0_D0/UART2_TX_M1/UART6_TX_M1/PWM8_M1/GPIO1_D5_u, 69 VCC3V3_SD, 70 CIF_CLKIN/EBC_SDCLK/GMAC1_MCLKINOUT_M1/UART1_CTSn_M1/I2S2_SCLK_RX_M1/GPIO4_C1_d, 71 CIF_CLKOUT/EBC_GDCLK/PWM11_IR_M1/GPIO4_C0_d, 72 CIF_VSYNC/EBC_SDOE/GMAC1_MDIO_M1/I2S2_SCLK_TX_M1/GPIO4_B7_d, 73 CIF_HREF/EBC_SDLE/GMAC1_MDC_M1/UART1_RTSn_M1/I2S2_MCLK_M1/GPIO4_B6_d, 74 I2C2_SCL_M1/EBC_SDSHR/CAN2_TX_M0/I2S1_SDO3_M1/GPIO4_B5_d, 75 I2C2_SDA_M1/EBC_GDSP/CAN2_RX_M0/ISP_FLASH_TRIGIN/VOP_BT656_CLK_M1/GPIO4_B4_d, 76 I2C4_SCL_M0/EBC_GDOE/ETH1_REFCLKO_25M_M1/SPI3_CLK_M0/I2S2_SDO_M1/GPIO4_B3_d, 77 I2C4_SDA_M0/EBC_VCOM/GMAC1_RXER_M1/SPI3_MOSI_M0/I2S2_SDI_M1/GPIO4_B2_d, 78 ISP_PRELIGHT_TRIG/EBC_SDCE3/GMAC1_RXDV_CRS_M1/I2S1_SDO2_M1/GPIO4_B1_d (power), 79 CAM_CLKOUT1/EBC_SDCE2/GMAC1_RXD1_M1/SPI3_MISO_M0/I2S1_SDO1_M1/GPIO4_B0_d, 80 CAM_CLKOUT0/EBC_SDCE1/GMAC1_RXD0_M1/SPI3_CS1_M0/I2S1_LRCK_RX_M1/GPIO4_A7_d, 81 ISP_FLASHTRIGOUT/EBC_SDCE0/GMAC1_TXEN_M1/SPI3_CS0_M0/I2S1_SCLK_RX_M1/GPIO4_A6_d, 82 CIF_D15/EBC_SDDO15/GMAC1_TXD1_M1/UART9_RX_M2/I2S2_LRCK_RX_M1/GPIO4_A5_d, 83 CIF_D14/EBC_SDDO14/GMAC1_TXD0_M1/UART9_TX_M2/I2S2_LRCK_TX_M1/GPIO4_A4_d, 84 CIF_D13/EBC_SDDO13/GMAC1_RXCLK_M1/UART7_RX_M2/PDM_SDI3_M1/GPIO4_A3_d, 85 CIF_D12/EBC_SDDO12/GMAC1_RXD3_M1/UART7_TX_M2/PDM_SDI2_M1/GPIO4_A2_d, 86 CIF_D11/EBC_SDDO11/GMAC1_RXD2_M1/PDM_SDI1_M1/GPIO4_A1_d, 87 CIF_D10/EBC_SDDO10/GMAC1_TXCLK_M1/PDM_CLK1_M1/GPIO4_A0_d, 88 CIF_D9/EBC_SDDO9/GMAC1_TXD3_M1/UART1_RX_M1/PDM_SDI0_M1/GPIO3_D7_d, 89 CIF_D8/EBC_SDDO8/GMAC1_TXD2_M1/UART1_TX_M1/PDM_CLK0_M1/GPIO3_D6_d, 90 CIF_D7/EBC_SDDO7/SDMMC2_PWREN_M0/I2S1_SDI3_M1/VOP_BT656_D7_M1/GPIO3_D5_d, 91 CIF_D6/EBC_SDDO6/SDMMC2_DET_M0/I2S1_SDI2_M1/VOP_BT656_D6_M1/GPIO3_D4_d, 92 CIF_D5/EBC_SDDO5/SDMMC2_CLK_M0/I2S1_SDI1_M1/VOP_BT656_D5_M1/GPIO3_D3_d, 93 CIF_D4/EBC_SDDO4/SDMMC2_CMD_M0/I2S1_SDI0_M1/VOP_BT656_D4_M1/GPIO3_D2_d, 94 CIF_D3/EBC_SDDO3/SDMMC2_D3_M0/I2S1_SDO0_M1/VOP_BT656_D3_M1/GPIO3_D1_d, 95 CIF_D2/EBC_SDDO2/SDMMC2_D2_M0/I2S1_LRCK_TX_M1/VOP_BT656_D2_M1/GPIO3_D0_d, 96 CIF_D1/EBC_SDDO1/SDMMC2_D1_M0/I2S1_SCLK_TX_M1/VOP_BT656_D1_M1/GPIO3_C7_d, 97 CIF_D0/EBC_SDDO0/SDMMC2_D0_M0/I2S1_MCLK_M1/VOP_BT656_D0_M1/GPIO3_C6_d, 98 GND5, 99 USB2_HOST2_DM, 100 USB2_HOST2_DP, 101 USB2_HOST3_DM (power), 102 USB2_HOST3_DP, 103 VCC_1V8, 104 VCC_3V3, 105 GND6, 106 PWM15_IR_M0/SPDIF_TX_M1/GMAC1_MDIO_M0/UART7_RX_M1/I2S1_LRCK_RX_M2/GPIO3_C5_d, 107 PWM14_M0/VOP_PWM_M1/GMAC1_MDC_M0/UART7_TX_M1/PDM_CLK1_M2/GPIO3_C4_d, 108 LCDC_DEN/VOP_BT1120_D15/SPI1_CLK_M1/UART5_RX_M1/I2S1_SCLK_RX_M2/GPIO3_C3_d, 109 LCDC_VSYNC/VOP_BT1120_D14/SPI1_MISO_M1/UART5_TX_M1/I2S1_SDO3_M2/GPIO3_C2_d, 110 LCDC_HSYNC/VOP_BT1120_D13/SPI1_MOSI_M1/PCIE20_PERSTn_M1/I2S1_SDO2_M2/GPIO3_C1_d, 111 LCDC_D23/PWM13_M0/GMAC1_MCLKINOUT_M0/UART3_RX_M1/PDM_SDI3_M2/GPIO3_C0_d, 112 LCDC_D22/PWM12_M0/GMAC1_TXEN_M0/UART3_TX_M1/PDM_SDI2_M2/GPIO3_B7_d, 113 LCDC_D21/VOP_BT1120_D12/GMAC1_TXD1_M0/I2C3_SDA_M1/PWM11_IR_M0/GPIO3_B6_d, 114 LCDC_D20/VOP_BT1120_D11/GMAC1_TXD0_M0/I2C3_SCL_M1/PWM10_M0/GPIO3_B5_d, 115 LCDC_D19/VOP_BT1120_D10/GMAC1_RXER_M0/I2C5_SDA_M0/PDM_SDI1_M2/GPIO3_B4_d, 116 LCDC_D18/VOP_BT1120_D9/GMAC1_RXDV_CRS_M0/I2C5_SCL_M0/PDM_SDI0_M2/GPIO3_B3_d, 117 LCDC_D17/VOP_BT1120_D8/GMAC1_RXD1_M0/UART4_TX_M1/PWM9_M0/GPIO3_B2_d, 118 LCDC_D16/VOP_BT1120_D7/GMAC1_RXD0_M0/UART4_RX_M1/PWM8_M0/GPIO3_B1_d, 119 LCDC_D15/VOP_BT1120_D6/ETH1_REFCLKO_25M_M0/SDMMC2_PWREN_M1/GPIO3_B0_d, 120 LCDC_D14/VOP_BT1120_D5/GMAC1_RXCLK_M0/SDMMC2_DET_M1/GPIO3_A7_d, 121 LCDC_D13/VOP_BT1120_CLK/GMAC1_TXCLK_M0/I2S3_SDI_M0/SDMMC2_CLK_M1/GPIO3_A6_d, 122 LCDC_D12/VOP_BT1120_D4/GMAC1_RXD3_M0/I2S3_SDO_M0/SDMMC2_CMD_M1/GPIO3_A5_d (power), 123 LCDC_D11/VOP_BT1120_D3/GMAC1_RXD2_M0/I2S3_LRCK_M0/SDMMC2_D3_M1/GPIO3_A4_d, 124 LCDC_D10/VOP_BT1120_D2/GMAC1_TXD3_M0/I2S3_SCLK_M0/SDMMC2_D2_M1/GPIO3_A3_d, 125 LCDC_D9/VOP_BT1120_D1/GMAC1_TXD2_M0/I2S3_MCLK_M0/SDMMC2_D1_M1/GPIO3_A2_d, 126 LCDC_D8/VOP_BT1120_D0/SPI1_CS0_M1/PCIE30X1_PERSTn_M1/SDMMC2_D0_M1/GPIO3_A1_d, 127 GND7, 128 MIPI_DSI_TX1_D3N, 129 MIPI_DSI_TX1_D3P, 130 MIPI_DSI_TX1_D2N (power), 131 MIPI_DSI_TX1_D2P, 132 MIPI_DSI_TX1_CLKN, 133 MIPI_DSI_TX1_CLKP, 134 MIPI_DSI_TX1_D1N, 135 MIPI_DSI_TX1_D1P, 136 MIPI_DSI_TX1_D0N, 137 MIPI_DSI_TX1_D0P, 138 MIPI_DSI_TX0_D3N/LVDS_TX0_D3N, 139 MIPI_DSI_TX0_D3P/LVDS_TX0_D3P, 140 MIPI_DSI_TX0_D2N/LVDS_TX0_D2N, 141 MIPI_DSI_TX0_D2P/LVDS_TX0_D2P (power), 142 MIPI_DSI_TX0_CLKN/LVDS_TX0_CLKN (power), 143 MIPI_DSI_TX0_CLKP/LVDS_TX0_CLKP, 144 MIPI_DSI_TX0_D1N/LVDS_TX0_D1N, 145 MIPI_DSI_TX0_D1P/LVDS_TX0_D1P (power), 146 MIPI_DSI_TX0_D0N/LVDS_TX0_D0N (power), 147 MIPI_DSI_TX0_D0P/LVDS_TX0_D0P (power), 148 HDMI_TX_HPDIN (power), 149 HDMITX_SDA/I2C5_SDA_M1/GPIO4_D0_u, 150 HDMITX_SCL/I2C5_SCL_M1/GPIO4_C7_u, 151 HDMITX_CEC_M0/SPI3_CS1_M1/GPIO4_D1_u, 152 GND8, 153 HDMI_TX_CLKN, 154 HDMI_TX_CLKP, 155 HDMI_TX_D0N, 156 HDMI_TX_D0P, 157 HDMI_TX_D1N, 158 HDMI_TX_D1P, 159 HDMI_TX_D2N, 160 HDMI_TX_D2P (power), 161 MIPI_CSI_RX_D0P/PCIE30_TX0P, 162 MIPI_CSI_RX_D0N/PCIE30_TX0N, 163 MIPI_CSI_RX_D1P/PCIE30_TX1P, 164 MIPI_CSI_RX_D1N/PCIE30_TX1N, 165 MIPI_CSI_RX_D2P/PCIE30_RX0P, 166 MIPI_CSI_RX_D2N/PCIE30_RX0N, 167 MIPI_CSI_RX_D3P/PCIE30_RX1P, 168 MIPI_CSI_RX_D3N/PCIE30_RX1N, 169 MIPI_CSI_RX_CLK0P/PCIE30_REFCLKP_IN, 170 MIPI_CSI_RX_CLK0N/PCIE30_REFCLKN_IN, 171 MIPI_CSI_RX_CLK1P, 172 MIPI_CSI_RX_CLK1N, 173 PCIE20_TXP/SATA2_TXP/QSGMII_TXP_M1, 174 PCIE20_TXN/SATA2_TXN/QSGMII_TXN_M1, 175 PCIE20_RXP/SATA2_RXP/QSGMII_RXP_M1, 176 PCIE20_RXN/SATA2_RXN/QSGMII_RXN_M1, 177 PCIE20_REFCLKP, 178 PCIE20_REFCLKN, 179 GND9, 180 USB3_HOST1_SSTXP/SATA1_TXP/QSGMII_TXP_M0, 181 USB3_HOST1_SSTXN/SATA1_TXN/QSGMII_TXN_M0, 182 USB3_HOST1_DM, 183 USB3_HOST1_DP, 184 USB3_HOST1_SSRXP/SATA1_RXP/QSGMII_RXP_M0, 185 USB3_HOST1_SSRXN/SATA1_RXN/QSGMII_RXN_M0, 186 USB3_OTG0_SSTXP/SATA0_TXP, 187 USB3_OTG0_SSTXN/SATA0_TXN, 188 USB3_OTG0_DM, 189 USB3_OTG0_DP, 190 USB3_OTG0_SSRXP/SATA0_RXP, 191 USB3_OTG0_SSRXN/SATA0_RXN, 192 USB3_OTG0_VBUSDET, 193 USB3_OTG0_ID, 194 GND10, 195 EDP_TX_D3N, 196 EDP_TX_D3P, 197 EDP_TX_AUXN, 198 EDP_TX_AUXP, 199 EDP_TX_D2N, 200 EDP_TX_D2P, 201 EDP_TX_D1N, 202 EDP_TX_D1P (power), 203 EDP_TX_D0N, 204 EDP_TX_D0P

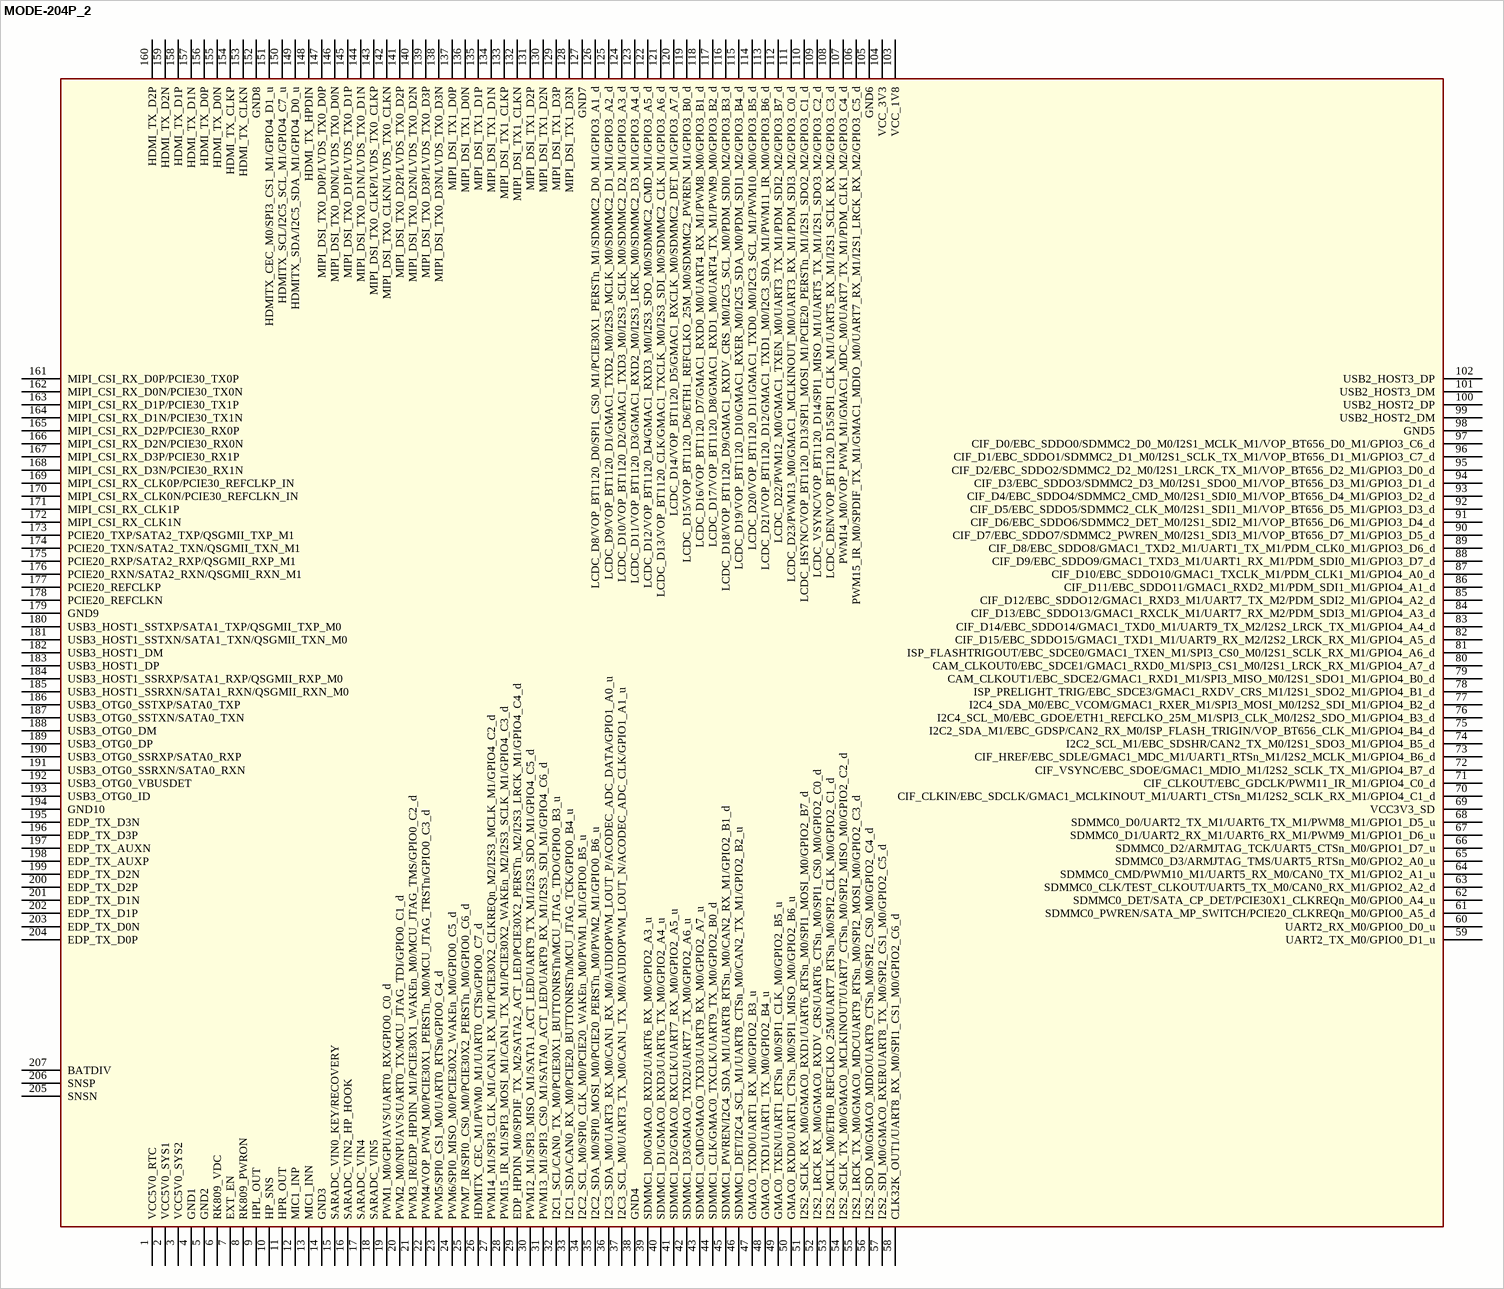
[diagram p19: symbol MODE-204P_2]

## MODE-204P_2
designator M?
Altium-Right: 1060; Altium-Bottom: 880
pins: 1 VCC5V0_RTC, 2 VCC5V0_SYS1, 3 VCC5V0_SYS2 (power), 4 GND1, 5 GND2, 6 RK809_VDC, 7 EXT_EN, 8 RK809_PWRON, 9 HPL_OUT, 10 HP_SNS, 11 HPR_OUT, 12 MIC1_INP, 13 MIC1_INN, 14 GND3, 15 SARADC_VIN0_KEY/RECOVERY, 16 SARADC_VIN2_HP_HOOK, 17 SARADC_VIN4, 18 SARADC_VIN5, 19 PWM1_M0/GPUAVS/UART0_RX/GPIO0_C0_d, 20 PWM2_M0/NPUAVS/UART0_TX/MCU_JTAG_TDI/GPIO0_C1_d, 21 PWM3_IR/EDP_HPDIN_M1/PCIE30X1_WAKEn_M0/MCU_JTAG_TMS/GPIO0_C2_d, 22 PWM4/VOP_PWM_M0/PCIE30X1_PERSTn_M0/MCU_JTAG_TRSTn/GPIO0_C3_d, 23 PWM5/SPI0_CS1_M0/UART0_RTSn/GPIO0_C4_d, 24 PWM6/SPI0_MISO_M0/PCIE30X2_WAKEn_M0/GPIO0_C5_d, 25 PWM7_IR/SPI0_CS0_M0/PCIE30X2_PERSTn_M0/GPIO0_C6_d, 26 HDMITX_CEC_M1/PWM0_M1/UART0_CTSn/GPIO0_C7_d (power), 27 PWM14_M1/SPI3_CLK_M1/CAN1_RX_M1/PCIE30X2_CLKREQn_M2/I2S3_MCLK_M1/GPIO4_C2_d, 28 PWM15_IR_M1/SPI3_MOSI_M1/CAN1_TX_M1/PCIE30X2_WAKEn_M2/I2S3_SCLK_M1/GPIO4_C3_d, 29 EDP_HPDIN_M0/SPDIF_TX_M2/SATA2_ACT_LED/PCIE30X2_PERSTn_M2/I2S3_LRCK_M1/GPIO4_C4_d, 30 PWM12_M1/SPI3_MISO_M1/SATA1_ACT_LED/UART9_TX_M1/I2S3_SDO_M1/GPIO4_C5_d, 31 PWM13_M1/SPI3_CS0_M1/SATA0_ACT_LED/UART9_RX_M1/I2S3_SDI_M1/GPIO4_C6_d, 32 I2C1_SCL/CAN0_TX_M0/PCIE30X1_BUTTONRSTn/MCU_JTAG_TDO/GPIO0_B3_u, 33 I2C1_SDA/CAN0_RX_M0/PCIE20_BUTTONRSTn/MCU_JTAG_TCK/GPIO0_B4_u, 34 I2C2_SCL_M0/SPI0_CLK_M0/PCIE20_WAKEn_M0/PWM1_M1/GPIO0_B5_u, 35 I2C2_SDA_M0/SPI0_MOSI_M0/PCIE20_PERSTn_M0/PWM2_M1/GPIO0_B6_u, 36 I2C3_SDA_M0/UART3_RX_M0/CAN1_RX_M0/AUDIOPWM_LOUT_P/ACODEC_ADC_DATA/GPIO1_A0_u, 37 I2C3_SCL_M0/UART3_TX_M0/CAN1_TX_M0/AUDIOPWM_LOUT_N/ACODEC_ADC_CLK/GPIO1_A1_u, 38 GND4, 39 SDMMC1_D0/GMAC0_RXD2/UART6_RX_M0/GPIO2_A3_u, 40 SDMMC1_D1/GMAC0_RXD3/UART6_TX_M0/GPIO2_A4_u, 41 SDMMC1_D2/GMAC0_RXCLK/UART7_RX_M0/GPIO2_A5_u, 42 SDMMC1_D3/GMAC0_TXD2/UART7_TX_M0/GPIO2_A6_u, 43 SDMMC1_CMD/GMAC0_TXD3/UART9_RX_M0/GPIO2_A7_u, 44 SDMMC1_CLK/GMAC0_TXCLK/UART9_TX_M0/GPIO2_B0_d, 45 SDMMC1_PWREN/I2C4_SDA_M1/UART8_RTSn_M0/CAN2_RX_M1/GPIO2_B1_d, 46 SDMMC1_DET/I2C4_SCL_M1/UART8_CTSn_M0/CAN2_TX_M1/GPIO2_B2_u, 47 GMAC0_TXD0/UART1_RX_M0/GPIO2_B3_u, 48 GMAC0_TXD1/UART1_TX_M0/GPIO2_B4_u (power), 49 GMAC0_TXEN/UART1_RTSn_M0/SPI1_CLK_M0/GPIO2_B5_u (power), 50 GMAC0_RXD0/UART1_CTSn_M0/SPI1_MISO_M0/GPIO2_B6_u, 51 I2S2_SCLK_RX_M0/GMAC0_RXD1/UART6_RTSn_M0/SPI1_MOSI_M0/GPIO2_B7_d, 52 I2S2_LRCK_RX_M0/GMAC0_RXDV_CRS/UART6_CTSn_M0/SPI1_CS0_M0/GPIO2_C0_d, 53 I2S2_MCLK_M0/ETH0_REFCLKO_25M/UART7_RTSn_M0/SPI2_CLK_M0/GPIO2_C1_d, 54 I2S2_SCLK_TX_M0/GMAC0_MCLKINOUT/UART7_CTSn_M0/SPI2_MISO_M0/GPIO2_C2_d, 55 I2S2_LRCK_TX_M0/GMAC0_MDC/UART9_RTSn_M0/SPI2_MOSI_M0/GPIO2_C3_d, 56 I2S2_SDO_M0/GMAC0_MDIO/UART9_CTSn_M0/SPI2_CS0_M0/GPIO2_C4_d, 57 I2S2_SDI_M0/GMAC0_RXER/UART8_TX_M0/SPI2_CS1_M0/GPIO2_C5_d, 58 CLK32K_OUT1/UART8_RX_M0/SPI1_CS1_M0/GPIO2_C6_d, 59 UART2_TX_M0/GPIO0_D1_u, 60 UART2_RX_M0/GPIO0_D0_u, 61 SDMMC0_PWREN/SATA_MP_SWITCH/PCIE20_CLKREQn_M0/GPIO0_A5_d, 62 SDMMC0_DET/SATA_CP_DET/PCIE30X1_CLKREQn_M0/GPIO0_A4_u, 63 SDMMC0_CLK/TEST_CLKOUT/UART5_TX_M0/CAN0_RX_M1/GPIO2_A2_d, 64 SDMMC0_CMD/PWM10_M1/UART5_RX_M0/CAN0_TX_M1/GPIO2_A1_u (power), 65 SDMMC0_D3/ARMJTAG_TMS/UART5_RTSn_M0/GPIO2_A0_u, 66 SDMMC0_D2/ARMJTAG_TCK/UART5_CTSn_M0/GPIO1_D7_u, 67 SDMMC0_D1/UART2_RX_M1/UART6_RX_M1/PWM9_M1/GPIO1_D6_u, 68 SDMMC0_D0/UART2_TX_M1/UART6_TX_M1/PWM8_M1/GPIO1_D5_u, 69 VCC3V3_SD, 70 CIF_CLKIN/EBC_SDCLK/GMAC1_MCLKINOUT_M1/UART1_CTSn_M1/I2S2_SCLK_RX_M1/GPIO4_C1_d, 71 CIF_CLKOUT/EBC_GDCLK/PWM11_IR_M1/GPIO4_C0_d, 72 CIF_VSYNC/EBC_SDOE/GMAC1_MDIO_M1/I2S2_SCLK_TX_M1/GPIO4_B7_d, 73 CIF_HREF/EBC_SDLE/GMAC1_MDC_M1/UART1_RTSn_M1/I2S2_MCLK_M1/GPIO4_B6_d, 74 I2C2_SCL_M1/EBC_SDSHR/CAN2_TX_M0/I2S1_SDO3_M1/GPIO4_B5_d, 75 I2C2_SDA_M1/EBC_GDSP/CAN2_RX_M0/ISP_FLASH_TRIGIN/VOP_BT656_CLK_M1/GPIO4_B4_d, 76 I2C4_SCL_M0/EBC_GDOE/ETH1_REFCLKO_25M_M1/SPI3_CLK_M0/I2S2_SDO_M1/GPIO4_B3_d, 77 I2C4_SDA_M0/EBC_VCOM/GMAC1_RXER_M1/SPI3_MOSI_M0/I2S2_SDI_M1/GPIO4_B2_d, 78 ISP_PRELIGHT_TRIG/EBC_SDCE3/GMAC1_RXDV_CRS_M1/I2S1_SDO2_M1/GPIO4_B1_d (power), 79 CAM_CLKOUT1/EBC_SDCE2/GMAC1_RXD1_M1/SPI3_MISO_M0/I2S1_SDO1_M1/GPIO4_B0_d, 80 CAM_CLKOUT0/EBC_SDCE1/GMAC1_RXD0_M1/SPI3_CS1_M0/I2S1_LRCK_RX_M1/GPIO4_A7_d, 81 ISP_FLASHTRIGOUT/EBC_SDCE0/GMAC1_TXEN_M1/SPI3_CS0_M0/I2S1_SCLK_RX_M1/GPIO4_A6_d, 82 CIF_D15/EBC_SDDO15/GMAC1_TXD1_M1/UART9_RX_M2/I2S2_LRCK_RX_M1/GPIO4_A5_d, 83 CIF_D14/EBC_SDDO14/GMAC1_TXD0_M1/UART9_TX_M2/I2S2_LRCK_TX_M1/GPIO4_A4_d, 84 CIF_D13/EBC_SDDO13/GMAC1_RXCLK_M1/UART7_RX_M2/PDM_SDI3_M1/GPIO4_A3_d, 85 CIF_D12/EBC_SDDO12/GMAC1_RXD3_M1/UART7_TX_M2/PDM_SDI2_M1/GPIO4_A2_d, 86 CIF_D11/EBC_SDDO11/GMAC1_RXD2_M1/PDM_SDI1_M1/GPIO4_A1_d, 87 CIF_D10/EBC_SDDO10/GMAC1_TXCLK_M1/PDM_CLK1_M1/GPIO4_A0_d, 88 CIF_D9/EBC_SDDO9/GMAC1_TXD3_M1/UART1_RX_M1/PDM_SDI0_M1/GPIO3_D7_d, 89 CIF_D8/EBC_SDDO8/GMAC1_TXD2_M1/UART1_TX_M1/PDM_CLK0_M1/GPIO3_D6_d, 90 CIF_D7/EBC_SDDO7/SDMMC2_PWREN_M0/I2S1_SDI3_M1/VOP_BT656_D7_M1/GPIO3_D5_d, 91 CIF_D6/EBC_SDDO6/SDMMC2_DET_M0/I2S1_SDI2_M1/VOP_BT656_D6_M1/GPIO3_D4_d, 92 CIF_D5/EBC_SDDO5/SDMMC2_CLK_M0/I2S1_SDI1_M1/VOP_BT656_D5_M1/GPIO3_D3_d, 93 CIF_D4/EBC_SDDO4/SDMMC2_CMD_M0/I2S1_SDI0_M1/VOP_BT656_D4_M1/GPIO3_D2_d, 94 CIF_D3/EBC_SDDO3/SDMMC2_D3_M0/I2S1_SDO0_M1/VOP_BT656_D3_M1/GPIO3_D1_d, 95 CIF_D2/EBC_SDDO2/SDMMC2_D2_M0/I2S1_LRCK_TX_M1/VOP_BT656_D2_M1/GPIO3_D0_d, 96 CIF_D1/EBC_SDDO1/SDMMC2_D1_M0/I2S1_SCLK_TX_M1/VOP_BT656_D1_M1/GPIO3_C7_d, 97 CIF_D0/EBC_SDDO0/SDMMC2_D0_M0/I2S1_MCLK_M1/VOP_BT656_D0_M1/GPIO3_C6_d, 98 GND5, 99 USB2_HOST2_DM, 100 USB2_HOST2_DP, 101 USB2_HOST3_DM (power), 102 USB2_HOST3_DP, 103 VCC_1V8, 104 VCC_3V3, 105 GND6, 106 PWM15_IR_M0/SPDIF_TX_M1/GMAC1_MDIO_M0/UART7_RX_M1/I2S1_LRCK_RX_M2/GPIO3_C5_d, 107 PWM14_M0/VOP_PWM_M1/GMAC1_MDC_M0/UART7_TX_M1/PDM_CLK1_M2/GPIO3_C4_d, 108 LCDC_DEN/VOP_BT1120_D15/SPI1_CLK_M1/UART5_RX_M1/I2S1_SCLK_RX_M2/GPIO3_C3_d, 109 LCDC_VSYNC/VOP_BT1120_D14/SPI1_MISO_M1/UART5_TX_M1/I2S1_SDO3_M2/GPIO3_C2_d, 110 LCDC_HSYNC/VOP_BT1120_D13/SPI1_MOSI_M1/PCIE20_PERSTn_M1/I2S1_SDO2_M2/GPIO3_C1_d, 111 LCDC_D23/PWM13_M0/GMAC1_MCLKINOUT_M0/UART3_RX_M1/PDM_SDI3_M2/GPIO3_C0_d, 112 LCDC_D22/PWM12_M0/GMAC1_TXEN_M0/UART3_TX_M1/PDM_SDI2_M2/GPIO3_B7_d, 113 LCDC_D21/VOP_BT1120_D12/GMAC1_TXD1_M0/I2C3_SDA_M1/PWM11_IR_M0/GPIO3_B6_d, 114 LCDC_D20/VOP_BT1120_D11/GMAC1_TXD0_M0/I2C3_SCL_M1/PWM10_M0/GPIO3_B5_d, 115 LCDC_D19/VOP_BT1120_D10/GMAC1_RXER_M0/I2C5_SDA_M0/PDM_SDI1_M2/GPIO3_B4_d, 116 LCDC_D18/VOP_BT1120_D9/GMAC1_RXDV_CRS_M0/I2C5_SCL_M0/PDM_SDI0_M2/GPIO3_B3_d, 117 LCDC_D17/VOP_BT1120_D8/GMAC1_RXD1_M0/UART4_TX_M1/PWM9_M0/GPIO3_B2_d, 118 LCDC_D16/VOP_BT1120_D7/GMAC1_RXD0_M0/UART4_RX_M1/PWM8_M0/GPIO3_B1_d, 119 LCDC_D15/VOP_BT1120_D6/ETH1_REFCLKO_25M_M0/SDMMC2_PWREN_M1/GPIO3_B0_d, 120 LCDC_D14/VOP_BT1120_D5/GMAC1_RXCLK_M0/SDMMC2_DET_M1/GPIO3_A7_d, 121 LCDC_D13/VOP_BT1120_CLK/GMAC1_TXCLK_M0/I2S3_SDI_M0/SDMMC2_CLK_M1/GPIO3_A6_d, 122 LCDC_D12/VOP_BT1120_D4/GMAC1_RXD3_M0/I2S3_SDO_M0/SDMMC2_CMD_M1/GPIO3_A5_d (power), 123 LCDC_D11/VOP_BT1120_D3/GMAC1_RXD2_M0/I2S3_LRCK_M0/SDMMC2_D3_M1/GPIO3_A4_d, 124 LCDC_D10/VOP_BT1120_D2/GMAC1_TXD3_M0/I2S3_SCLK_M0/SDMMC2_D2_M1/GPIO3_A3_d, 125 LCDC_D9/VOP_BT1120_D1/GMAC1_TXD2_M0/I2S3_MCLK_M0/SDMMC2_D1_M1/GPIO3_A2_d, 126 LCDC_D8/VOP_BT1120_D0/SPI1_CS0_M1/PCIE30X1_PERSTn_M1/SDMMC2_D0_M1/GPIO3_A1_d, 127 GND7, 128 MIPI_DSI_TX1_D3N, 129 MIPI_DSI_TX1_D3P, 130 MIPI_DSI_TX1_D2N (power), 131 MIPI_DSI_TX1_D2P, 132 MIPI_DSI_TX1_CLKN, 133 MIPI_DSI_TX1_CLKP, 134 MIPI_DSI_TX1_D1N, 135 MIPI_DSI_TX1_D1P, 136 MIPI_DSI_TX1_D0N, 137 MIPI_DSI_TX1_D0P, 138 MIPI_DSI_TX0_D3N/LVDS_TX0_D3N, 139 MIPI_DSI_TX0_D3P/LVDS_TX0_D3P, 140 MIPI_DSI_TX0_D2N/LVDS_TX0_D2N, 141 MIPI_DSI_TX0_D2P/LVDS_TX0_D2P (power), 142 MIPI_DSI_TX0_CLKN/LVDS_TX0_CLKN (power), 143 MIPI_DSI_TX0_CLKP/LVDS_TX0_CLKP, 144 MIPI_DSI_TX0_D1N/LVDS_TX0_D1N, 145 MIPI_DSI_TX0_D1P/LVDS_TX0_D1P (power), 146 MIPI_DSI_TX0_D0N/LVDS_TX0_D0N (power), 147 MIPI_DSI_TX0_D0P/LVDS_TX0_D0P (power), 148 HDMI_TX_HPDIN (power), 149 HDMITX_SDA/I2C5_SDA_M1/GPIO4_D0_u, 150 HDMITX_SCL/I2C5_SCL_M1/GPIO4_C7_u, 151 HDMITX_CEC_M0/SPI3_CS1_M1/GPIO4_D1_u, 152 GND8, 153 HDMI_TX_CLKN, 154 HDMI_TX_CLKP, 155 HDMI_TX_D0N, 156 HDMI_TX_D0P, 157 HDMI_TX_D1N, 158 HDMI_TX_D1P, 159 HDMI_TX_D2N, 160 HDMI_TX_D2P (power), 161 MIPI_CSI_RX_D0P/PCIE30_TX0P, 162 MIPI_CSI_RX_D0N/PCIE30_TX0N, 163 MIPI_CSI_RX_D1P/PCIE30_TX1P, 164 MIPI_CSI_RX_D1N/PCIE30_TX1N, 165 MIPI_CSI_RX_D2P/PCIE30_RX0P, 166 MIPI_CSI_RX_D2N/PCIE30_RX0N, 167 MIPI_CSI_RX_D3P/PCIE30_RX1P, 168 MIPI_CSI_RX_D3N/PCIE30_RX1N, 169 MIPI_CSI_RX_CLK0P/PCIE30_REFCLKP_IN, 170 MIPI_CSI_RX_CLK0N/PCIE30_REFCLKN_IN, 171 MIPI_CSI_RX_CLK1P, 172 MIPI_CSI_RX_CLK1N, 173 PCIE20_TXP/SATA2_TXP/QSGMII_TXP_M1, 174 PCIE20_TXN/SATA2_TXN/QSGMII_TXN_M1, 175 PCIE20_RXP/SATA2_RXP/QSGMII_RXP_M1, 176 PCIE20_RXN/SATA2_RXN/QSGMII_RXN_M1, 177 PCIE20_REFCLKP, 178 PCIE20_REFCLKN, 179 GND9, 180 USB3_HOST1_SSTXP/SATA1_TXP/QSGMII_TXP_M0, 181 USB3_HOST1_SSTXN/SATA1_TXN/QSGMII_TXN_M0, 182 USB3_HOST1_DM, 183 USB3_HOST1_DP, 184 USB3_HOST1_SSRXP/SATA1_RXP/QSGMII_RXP_M0, 185 USB3_HOST1_SSRXN/SATA1_RXN/QSGMII_RXN_M0, 186 USB3_OTG0_SSTXP/SATA0_TXP, 187 USB3_OTG0_SSTXN/SATA0_TXN, 188 USB3_OTG0_DM, 189 USB3_OTG0_DP, 190 USB3_OTG0_SSRXP/SATA0_RXP, 191 USB3_OTG0_SSRXN/SATA0_RXN, 192 USB3_OTG0_VBUSDET, 193 USB3_OTG0_ID, 194 GND10, 195 EDP_TX_D3N, 196 EDP_TX_D3P, 197 EDP_TX_AUXN, 198 EDP_TX_AUXP, 199 EDP_TX_D2N, 200 EDP_TX_D2P, 201 EDP_TX_D1N, 202 EDP_TX_D1P (power), 203 EDP_TX_D0N, 204 EDP_TX_D0P, 205 SNSN, 206 SNSP, 207 BATDIV

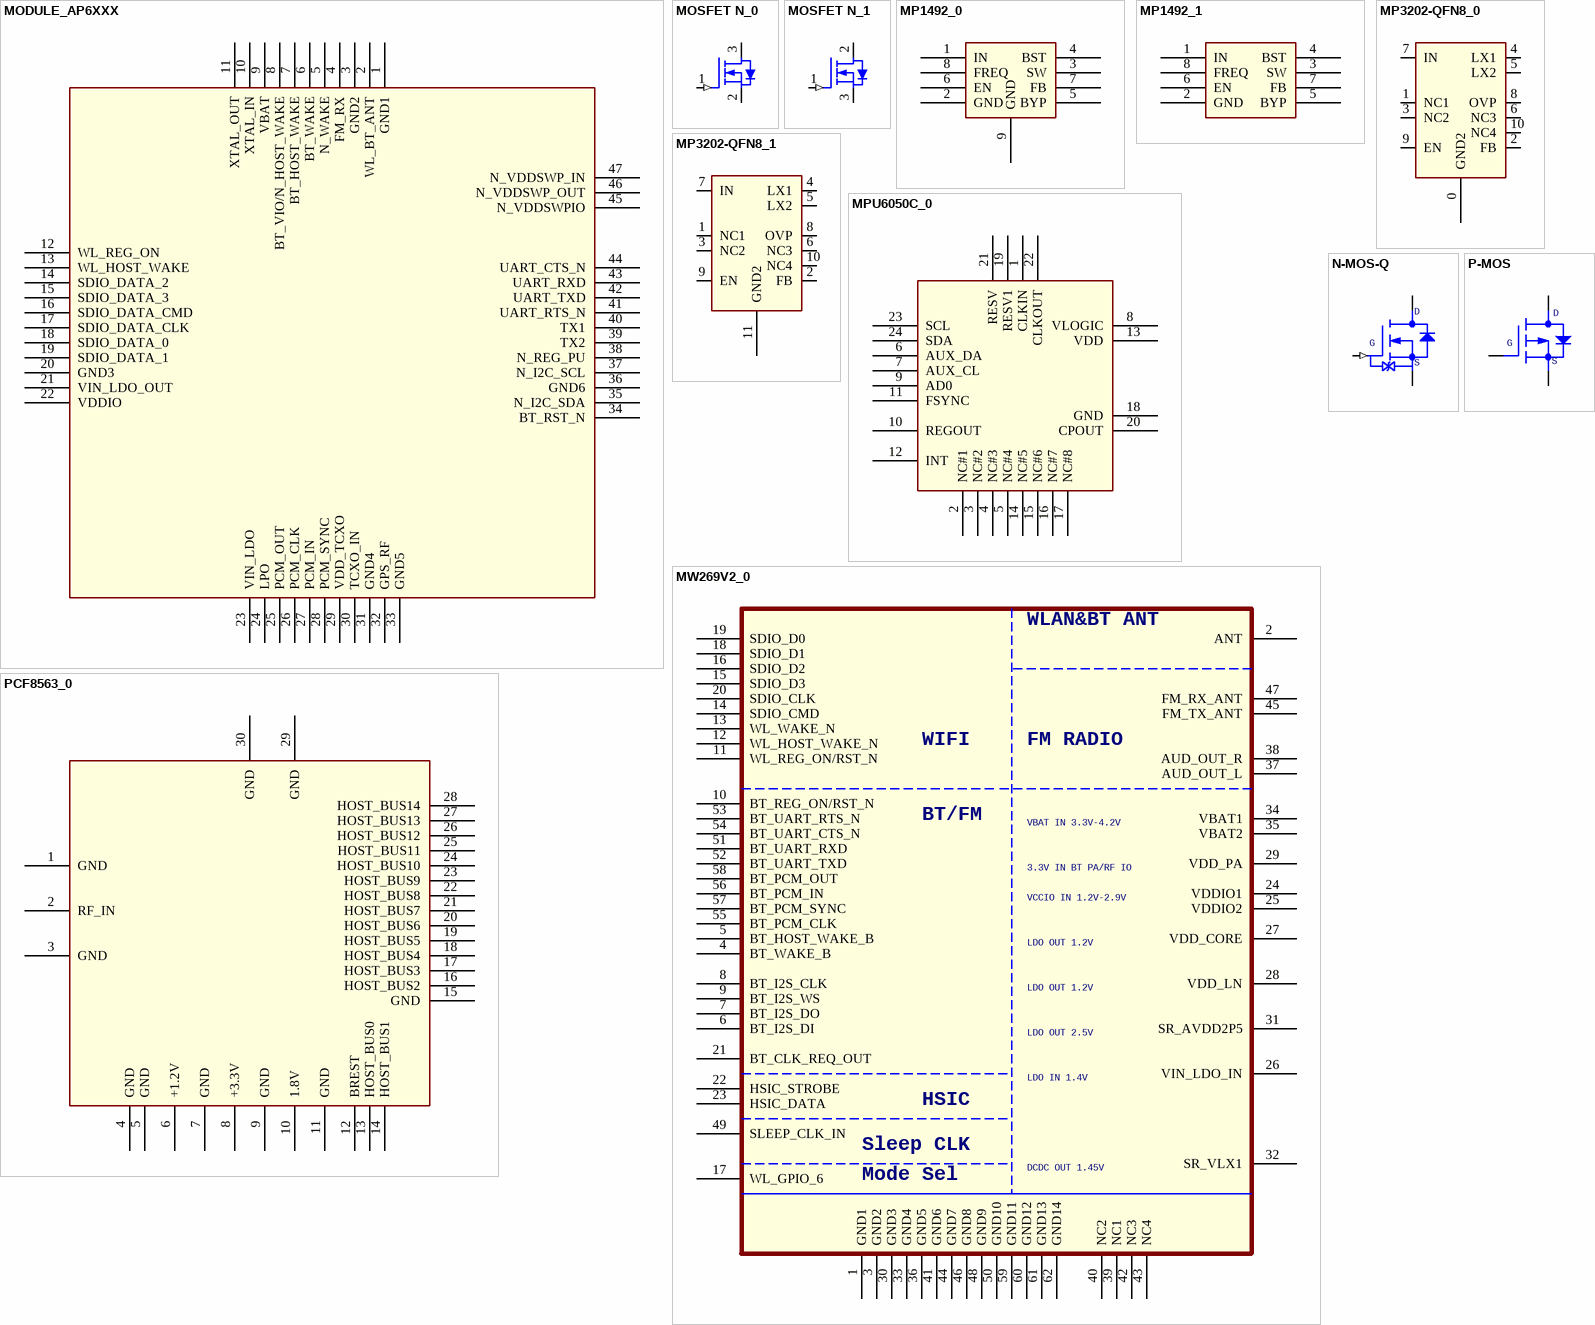
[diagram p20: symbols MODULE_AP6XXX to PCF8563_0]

## MODULE_AP6XXX
designator U?
Altium-Right: 350; Altium-Bottom: 340
pins: 1 GND1, 2 WL_BT_ANT, 3 GND2, 4 FM_RX, 5 N_WAKE, 6 BT_WAKE, 7 BT_HOST_WAKE, 8 BT_VIO/N_HOST_WAKE, 9 VBAT, 10 XTAL_IN, 11 XTAL_OUT, 12 WL_REG_ON, 13 WL_HOST_WAKE, 14 SDIO_DATA_2, 15 SDIO_DATA_3, 16 SDIO_DATA_CMD, 17 SDIO_DATA_CLK, 18 SDIO_DATA_0, 19 SDIO_DATA_1, 20 GND3, 21 VIN_LDO_OUT, 22 VDDIO, 23 VIN_LDO, 24 LPO, 25 PCM_OUT, 26 PCM_CLK, 27 PCM_IN, 28 PCM_SYNC, 29 VDD_TCXO, 30 TCXO_IN, 31 GND4, 32 GPS_RF, 33 GND5, 34 BT_RST_N, 35 N_I2C_SDA, 36 GND6, 37 N_I2C_SCL, 38 N_REG_PU, 39 TX2, 40 TX1, 41 UART_RTS_N, 42 UART_TXD, 43 UART_RXD, 44 UART_CTS_N, 45 N_VDDSWPIO, 46 N_VDDSWP_OUT, 47 N_VDDSWP_IN

## MOSFET N_0
designator Q?
Altium-Right: 30; Altium-Bottom: 20
pins: 1 GATE (in), 2 SOURCE, 3 DRAIN

## MOSFET N_1
designator Q?
Altium-Right: 30; Altium-Bottom: 20
pins: 1 GATE (in), 2 DRAIN, 3 SOURCE

## MP1492_0
designator U?
Altium-Right: 60; Altium-Bottom: 50
footprint SOP8A
pins: 1 IN, 2 GND, 3 SW, 4 BST, 5 BYP, 6 EN, 7 FB, 8 FREQ, 9 GND

## MP1492_1
designator U?
Altium-Right: 60; Altium-Bottom: 50
footprint SOP8A
pins: 1 IN, 2 GND, 3 SW, 4 BST, 5 BYP, 6 EN, 7 FB, 8 FREQ

## MP3202-QFN8_0
designator U?
Altium-Right: 60; Altium-Bottom: 90
footprint QFN8-2X2
pins: 0 GND2, 1 NC1, 2 FB, 3 NC2, 4 LX1, 5 LX2, 6 NC3, 7 IN, 8 OVP, 9 EN, 10 NC4

## MP3202-QFN8_1
designator U?
Altium-Right: 60; Altium-Bottom: 90
footprint QFN8-2X2
pins: 1 NC1, 2 FB, 3 NC2, 4 LX1, 5 LX2, 6 NC3, 7 IN, 8 OVP, 9 EN, 10 NC4, 11 GND2

## MPU6050C_0
designator U?
Altium-Right: 130; Altium-Bottom: 140
pins: 1 CLKIN, 2 NC#1, 3 NC#2, 4 NC#3, 5 NC#4, 6 AUX_DA, 7 AUX_CL, 8 VLOGIC, 9 AD0, 10 REGOUT, 11 FSYNC, 12 INT, 13 VDD, 14 NC#5, 15 NC#6, 16 NC#7, 17 NC#8, 18 GND, 19 RESV1, 20 CPOUT, 21 RESV, 22 CLKOUT, 23 SCL, 24 SDA

## MW269V2_0
designator U?
Altium-Right: 340; Altium-Bottom: 430
footprint MW269V2
pins: 1 GND1, 2 ANT, 3 GND2, 4 BT_WAKE_B, 5 BT_HOST_WAKE_B, 6 BT_I2S_DI, 7 BT_I2S_DO, 8 BT_I2S_CLK, 9 BT_I2S_WS, 10 BT_REG_ON/RST_N, 11 WL_REG_ON/RST_N, 12 WL_HOST_WAKE_N, 13 WL_WAKE_N, 14 SDIO_CMD, 15 SDIO_D3, 16 SDIO_D2, 17 WL_GPIO_6, 18 SDIO_D1, 19 SDIO_D0, 20 SDIO_CLK, 21 BT_CLK_REQ_OUT, 22 HSIC_STROBE, 23 HSIC_DATA, 24 VDDIO1, 25 VDDIO2, 26 VIN_LDO_IN, 27 VDD_CORE, 28 VDD_LN, 29 VDD_PA, 30 GND3, 31 SR_AVDD2P5, 32 SR_VLX1, 33 GND4, 34 VBAT1, 35 VBAT2, 36 GND5, 37 AUD_OUT_L, 38 AUD_OUT_R, 39 NC1, 40 NC2, 41 GND6, 42 NC3, 43 NC4, 44 GND7, 45 FM_TX_ANT, 46 GND8, 47 FM_RX_ANT, 48 GND9, 49 SLEEP_CLK_IN, 50 GND10, 51 BT_UART_RXD, 52 BT_UART_TXD, 53 BT_UART_RTS_N, 54 BT_UART_CTS_N, 55 BT_PCM_CLK, 56 BT_PCM_IN, 57 BT_PCM_SYNC, 58 BT_PCM_OUT, 59 GND11, 60 GND12, 61 GND13, 62 GND14

## N-MOS-Q
designator Q?
Altium-Right: 50; Altium-Bottom: 40
pins: 1 GATE (in), 2 SOURCE, 3 DRAIN

## P-MOS
designator Q?
Altium-Right: 50; Altium-Bottom: 40
pins: 1 GATE, 2 SOURCE, 3 DRAIN

## PCF8563_0
designator U?
Altium-Right: 240; Altium-Bottom: 230
footprint SOP-8
pins: 1 GND, 2 RF_IN, 3 GND, 4 GND, 5 GND, 6 +1.2V, 7 GND, 8 +3.3V, 9 GND, 10 1.8V, 11 GND, 12 BREST, 13 HOST_BUS0, 14 HOST_BUS1, 15 GND, 16 HOST_BUS2, 17 HOST_BUS3, 18 HOST_BUS4, 19 HOST_BUS5, 20 HOST_BUS6, 21 HOST_BUS7, 22 HOST_BUS8, 23 HOST_BUS9, 24 HOST_BUS10, 25 HOST_BUS11, 26 HOST_BUS12, 27 HOST_BUS13, 28 HOST_BUS14, 29 GND, 30 GND
1 alternate drawing of the same symbol

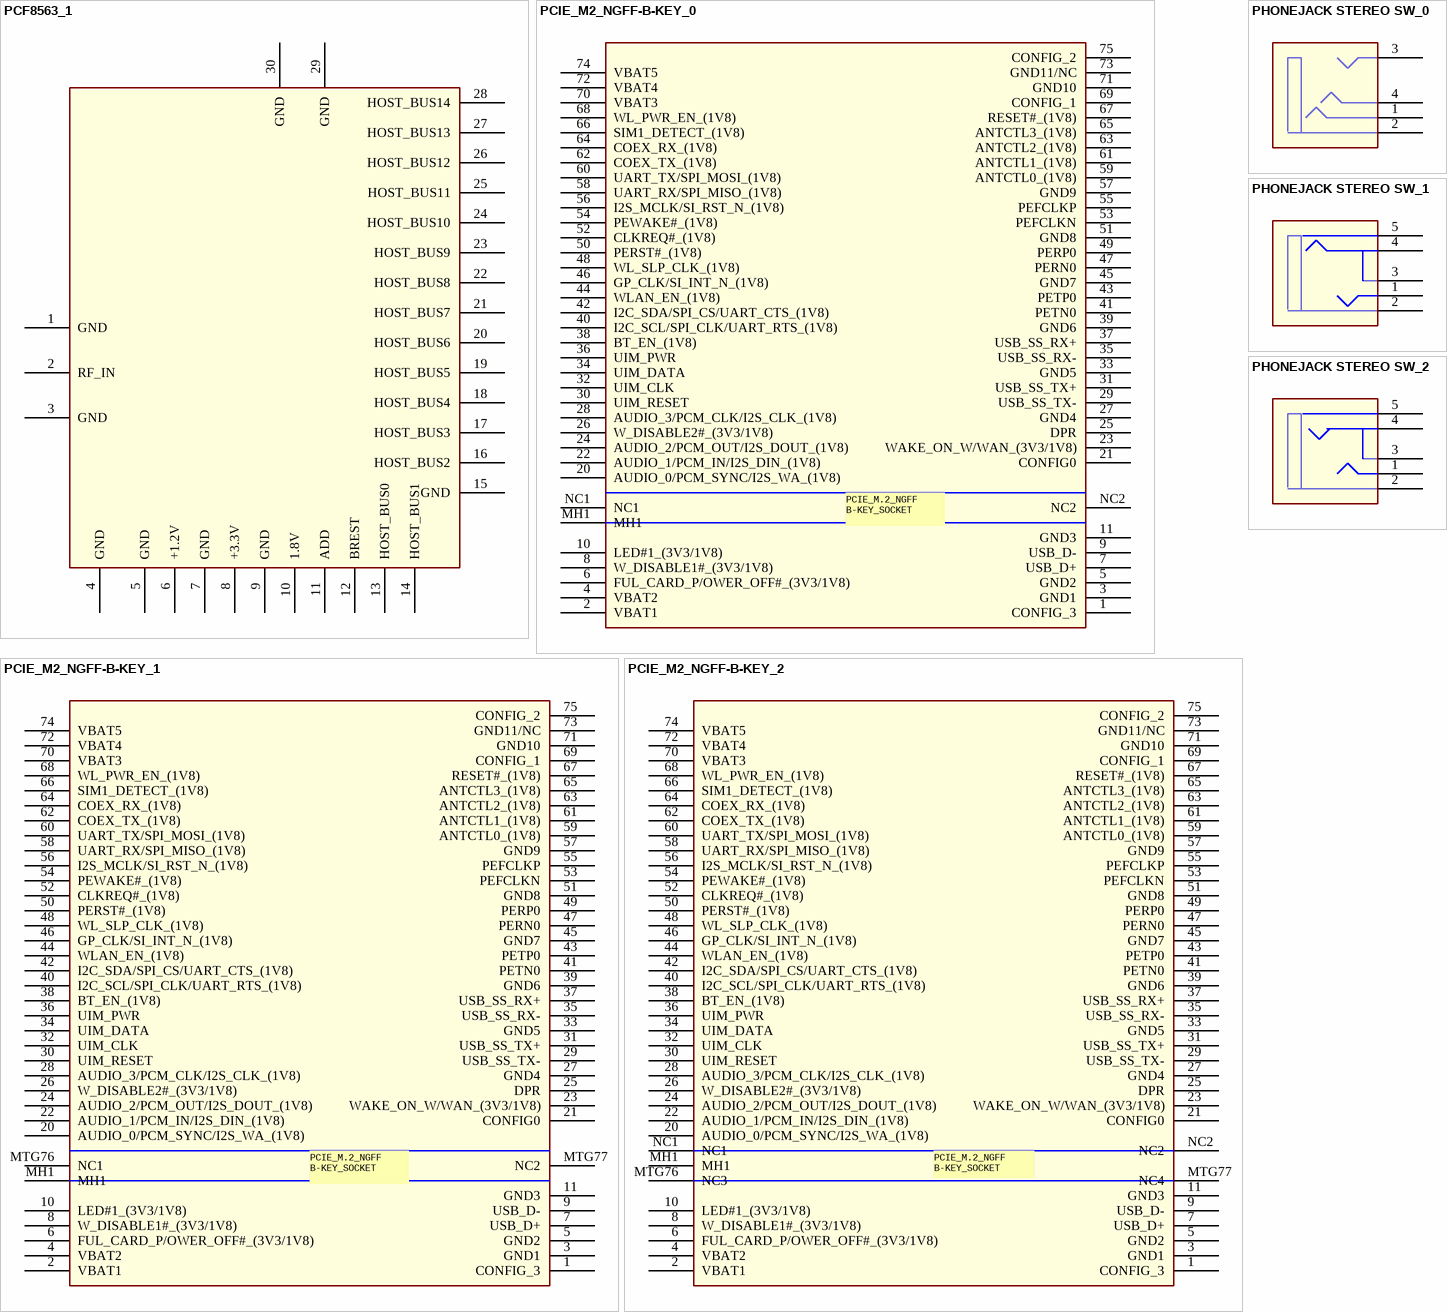
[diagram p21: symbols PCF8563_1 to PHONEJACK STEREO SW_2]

## PCF8563_1
designator U?
Altium-Right: 260; Altium-Bottom: 320
footprint SOP-8
pins: 1 GND, 2 RF_IN, 3 GND, 4 GND, 5 GND, 6 +1.2V, 7 GND, 8 +3.3V, 9 GND, 10 1.8V, 11 ADD, 12 BREST, 13 HOST_BUS0, 14 HOST_BUS1, 15 GND, 16 HOST_BUS2, 17 HOST_BUS3, 18 HOST_BUS4, 19 HOST_BUS5, 20 HOST_BUS6, 21 HOST_BUS7, 22 HOST_BUS8, 23 HOST_BUS9, 24 HOST_BUS10, 25 HOST_BUS11, 26 HOST_BUS12, 27 HOST_BUS13, 28 HOST_BUS14, 29 GND, 30 GND
1 alternate drawing of the same symbol

## PCIE_M2_NGFF-B-KEY_0
designator U?
Altium-Right: 320; Altium-Bottom: 390
pins: 1 CONFIG_3, 2 VBAT1, 3 GND1, 4 VBAT2, 5 GND2, 6 FUL_CARD_P/OWER_OFF#_(3V3/1V8), 7 USB_D+, 8 W_DISABLE1#_(3V3/1V8), 9 USB_D-, 10 LED#1_(3V3/1V8), 11 GND3, 20 AUDIO_0/PCM_SYNC/I2S_WA_(1V8), 21 CONFIG0, 22 AUDIO_1/PCM_IN/I2S_DIN_(1V8), 23 WAKE_ON_W/WAN_(3V3/1V8), 24 AUDIO_2/PCM_OUT/I2S_DOUT_(1V8), 25 DPR, 26 W_DISABLE2#_(3V3/1V8), 27 GND4, 28 AUDIO_3/PCM_CLK/I2S_CLK_(1V8), 29 USB_SS_TX-, 30 UIM_RESET, 31 USB_SS_TX+, 32 UIM_CLK, 33 GND5, 34 UIM_DATA, 35 USB_SS_RX-, 36 UIM_PWR, 37 USB_SS_RX+, 38 BT_EN_(1V8), 39 GND6, 40 I2C_SCL/SPI_CLK/UART_RTS_(1V8), 41 PETN0, 42 I2C_SDA/SPI_CS/UART_CTS_(1V8), 43 PETP0, 44 WLAN_EN_(1V8), 45 GND7, 46 GP_CLK/SI_INT_N_(1V8), 47 PERN0, 48 WL_SLP_CLK_(1V8), 49 PERP0, 50 PERST#_(1V8), 51 GND8, 52 CLKREQ#_(1V8), 53 PEFCLKN, 54 PEWAKE#_(1V8), 55 PEFCLKP, 56 I2S_MCLK/SI_RST_N_(1V8), 57 GND9, 58 UART_RX/SPI_MISO_(1V8), 59 ANTCTL0_(1V8), 60 UART_TX/SPI_MOSI_(1V8), 61 ANTCTL1_(1V8), 62 COEX_TX_(1V8), 63 ANTCTL2_(1V8), 64 COEX_RX_(1V8), 65 ANTCTL3_(1V8), 66 SIM1_DETECT_(1V8), 67 RESET#_(1V8), 68 WL_PWR_EN_(1V8), 69 CONFIG_1, 70 VBAT3, 71 GND10, 72 VBAT4, 73 GND11/NC, 74 VBAT5, 75 CONFIG_2, MH1, NC1, NC2

## PCIE_M2_NGFF-B-KEY_1
designator U?
Altium-Right: 320; Altium-Bottom: 390
pins: 1 CONFIG_3, 2 VBAT1, 3 GND1, 4 VBAT2, 5 GND2, 6 FUL_CARD_P/OWER_OFF#_(3V3/1V8), 7 USB_D+, 8 W_DISABLE1#_(3V3/1V8), 9 USB_D-, 10 LED#1_(3V3/1V8), 11 GND3, 20 AUDIO_0/PCM_SYNC/I2S_WA_(1V8), 21 CONFIG0, 22 AUDIO_1/PCM_IN/I2S_DIN_(1V8), 23 WAKE_ON_W/WAN_(3V3/1V8), 24 AUDIO_2/PCM_OUT/I2S_DOUT_(1V8), 25 DPR, 26 W_DISABLE2#_(3V3/1V8), 27 GND4, 28 AUDIO_3/PCM_CLK/I2S_CLK_(1V8), 29 USB_SS_TX-, 30 UIM_RESET, 31 USB_SS_TX+, 32 UIM_CLK, 33 GND5, 34 UIM_DATA, 35 USB_SS_RX-, 36 UIM_PWR, 37 USB_SS_RX+, 38 BT_EN_(1V8), 39 GND6, 40 I2C_SCL/SPI_CLK/UART_RTS_(1V8), 41 PETN0, 42 I2C_SDA/SPI_CS/UART_CTS_(1V8), 43 PETP0, 44 WLAN_EN_(1V8), 45 GND7, 46 GP_CLK/SI_INT_N_(1V8), 47 PERN0, 48 WL_SLP_CLK_(1V8), 49 PERP0, 50 PERST#_(1V8), 51 GND8, 52 CLKREQ#_(1V8), 53 PEFCLKN, 54 PEWAKE#_(1V8), 55 PEFCLKP, 56 I2S_MCLK/SI_RST_N_(1V8), 57 GND9, 58 UART_RX/SPI_MISO_(1V8), 59 ANTCTL0_(1V8), 60 UART_TX/SPI_MOSI_(1V8), 61 ANTCTL1_(1V8), 62 COEX_TX_(1V8), 63 ANTCTL2_(1V8), 64 COEX_RX_(1V8), 65 ANTCTL3_(1V8), 66 SIM1_DETECT_(1V8), 67 RESET#_(1V8), 68 WL_PWR_EN_(1V8), 69 CONFIG_1, 70 VBAT3, 71 GND10, 72 VBAT4, 73 GND11/NC, 74 VBAT5, 75 CONFIG_2, MH1, MTG76 NC1, MTG77 NC2

## PCIE_M2_NGFF-B-KEY_2
designator U?
Altium-Right: 320; Altium-Bottom: 390
pins: 1 CONFIG_3, 2 VBAT1, 3 GND1, 4 VBAT2, 5 GND2, 6 FUL_CARD_P/OWER_OFF#_(3V3/1V8), 7 USB_D+, 8 W_DISABLE1#_(3V3/1V8), 9 USB_D-, 10 LED#1_(3V3/1V8), 11 GND3, 20 AUDIO_0/PCM_SYNC/I2S_WA_(1V8), 21 CONFIG0, 22 AUDIO_1/PCM_IN/I2S_DIN_(1V8), 23 WAKE_ON_W/WAN_(3V3/1V8), 24 AUDIO_2/PCM_OUT/I2S_DOUT_(1V8), 25 DPR, 26 W_DISABLE2#_(3V3/1V8), 27 GND4, 28 AUDIO_3/PCM_CLK/I2S_CLK_(1V8), 29 USB_SS_TX-, 30 UIM_RESET, 31 USB_SS_TX+, 32 UIM_CLK, 33 GND5, 34 UIM_DATA, 35 USB_SS_RX-, 36 UIM_PWR, 37 USB_SS_RX+, 38 BT_EN_(1V8), 39 GND6, 40 I2C_SCL/SPI_CLK/UART_RTS_(1V8), 41 PETN0, 42 I2C_SDA/SPI_CS/UART_CTS_(1V8), 43 PETP0, 44 WLAN_EN_(1V8), 45 GND7, 46 GP_CLK/SI_INT_N_(1V8), 47 PERN0, 48 WL_SLP_CLK_(1V8), 49 PERP0, 50 PERST#_(1V8), 51 GND8, 52 CLKREQ#_(1V8), 53 PEFCLKN, 54 PEWAKE#_(1V8), 55 PEFCLKP, 56 I2S_MCLK/SI_RST_N_(1V8), 57 GND9, 58 UART_RX/SPI_MISO_(1V8), 59 ANTCTL0_(1V8), 60 UART_TX/SPI_MOSI_(1V8), 61 ANTCTL1_(1V8), 62 COEX_TX_(1V8), 63 ANTCTL2_(1V8), 64 COEX_RX_(1V8), 65 ANTCTL3_(1V8), 66 SIM1_DETECT_(1V8), 67 RESET#_(1V8), 68 WL_PWR_EN_(1V8), 69 CONFIG_1, 70 VBAT3, 71 GND10, 72 VBAT4, 73 GND11/NC, 74 VBAT5, 75 CONFIG_2, MH1, MTG76 NC3, MTG77 NC4, NC1, NC2

## PHONEJACK STEREO SW_0
designator J?
Altium-Right: 70
pins: 1 HP, 2 COM, 3 L, 4 R

## PHONEJACK STEREO SW_1
designator J?
Altium-Right: 70
footprint PHONE-ST-0166MT-050
pins: 1 R, 2 COM, 3 HP, 4 L, 5

## PHONEJACK STEREO SW_2
designator J?
Altium-Right: 70
footprint PHONE-ST-0166MT-050
pins: 1 R, 2 COM, 3 HP, 4 L, 5

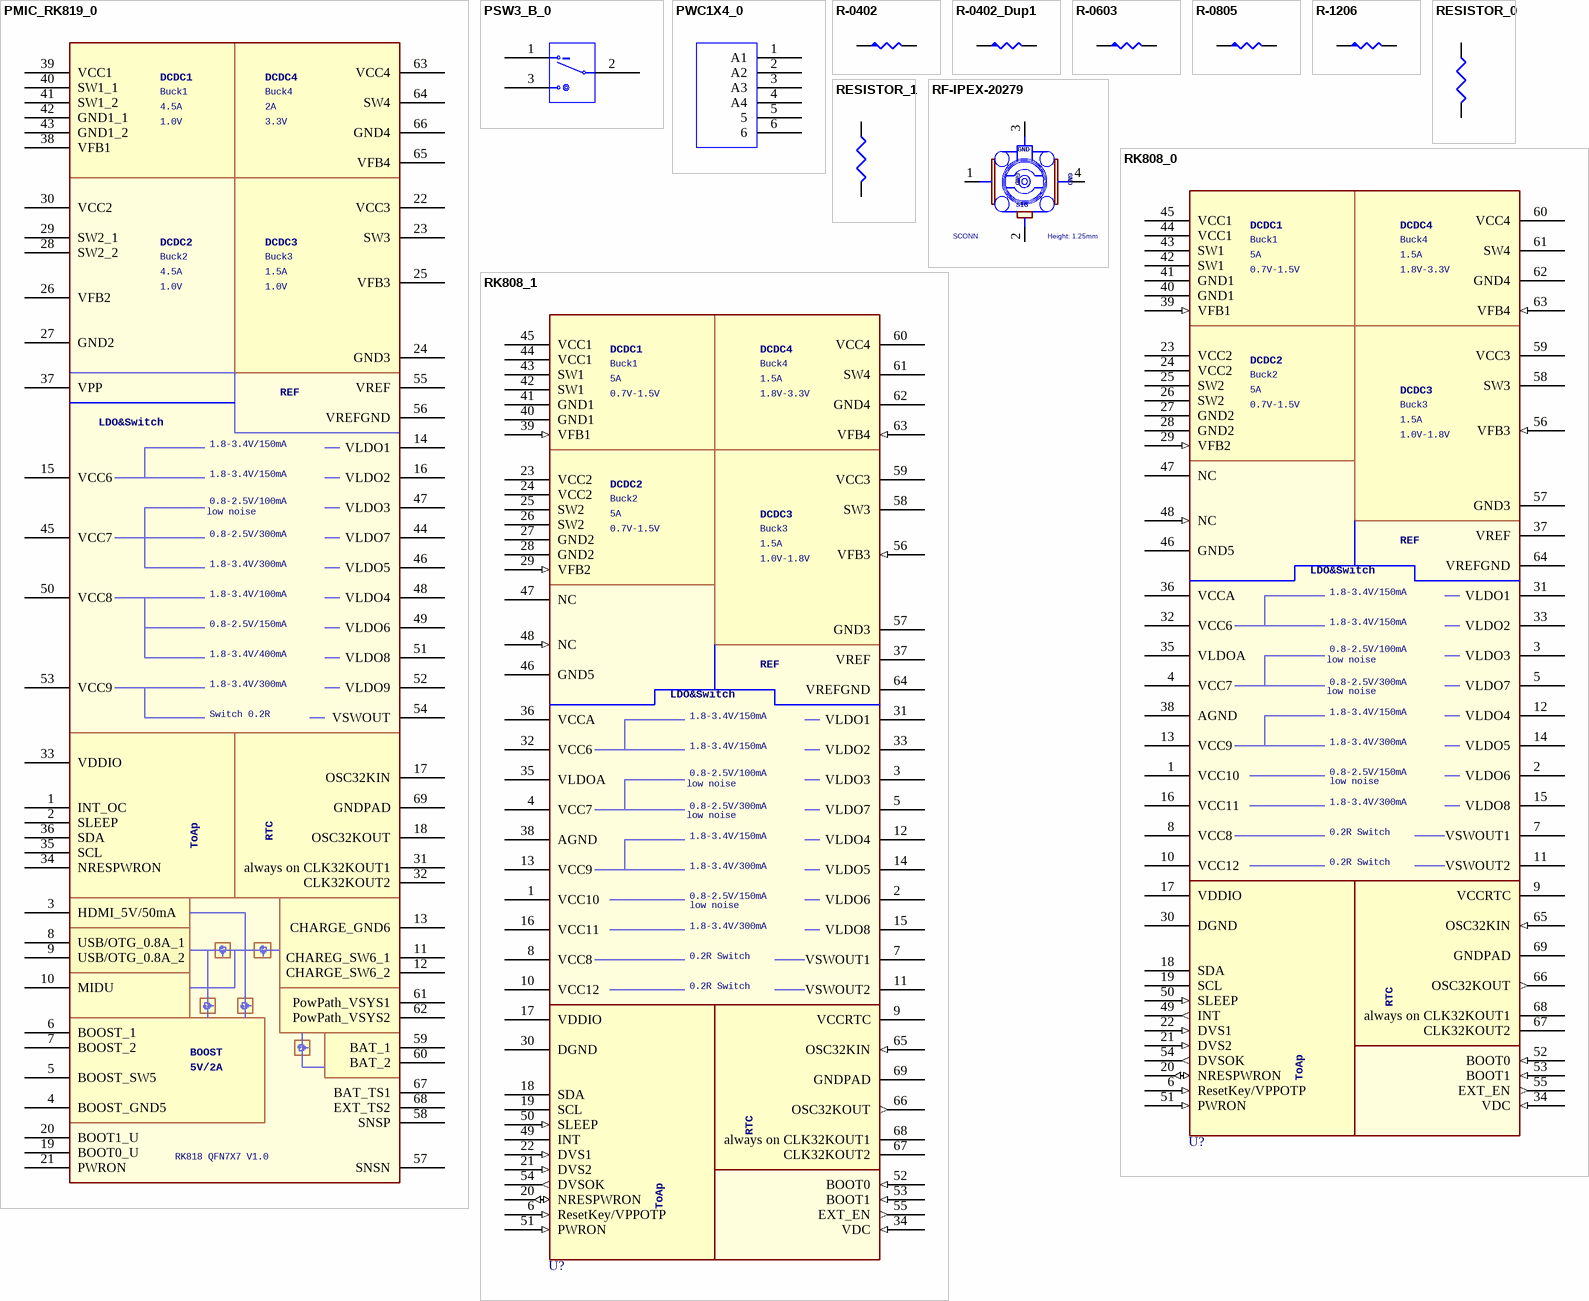
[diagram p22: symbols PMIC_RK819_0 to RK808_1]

## PMIC_RK819_0
designator U?
Altium-Right: 220; Altium-Bottom: 760
footprint QFN68
pins: 1 INT_OC, 2 SLEEP, 3 HDMI_5V/50mA, 4 BOOST_GND5, 5 BOOST_SW5, 6 BOOST_1, 7 BOOST_2, 8 USB/OTG_0.8A_1, 9 USB/OTG_0.8A_2, 10 MIDU, 11 CHAREG_SW6_1, 12 CHARGE_SW6_2, 13 CHARGE_GND6, 14 VLDO1, 15 VCC6, 16 VLDO2, 17 OSC32KIN, 18 OSC32KOUT, 19 BOOT0_U, 20 BOOT1_U, 21 PWRON, 22 VCC3, 23 SW3, 24 GND3, 25 VFB3, 26 VFB2, 27 GND2, 28 SW2_2, 29 SW2_1, 30 VCC2, 31 always on CLK32KOUT1, 32 CLK32KOUT2, 33 VDDIO, 34 NRESPWRON, 35 SCL, 36 SDA, 37 VPP, 38 VFB1, 39 VCC1, 40 SW1_1, 41 SW1_2, 42 GND1_1, 43 GND1_2, 44 VLDO7, 45 VCC7, 46 VLDO5, 47 VLDO3, 48 VLDO4, 49 VLDO6, 50 VCC8, 51 VLDO8, 52 VLDO9, 53 VCC9, 54 VSWOUT, 55 VREF, 56 VREFGND, 57 SNSN, 58 SNSP, 59 BAT_1, 60 BAT_2, 61 PowPath_VSYS1, 62 PowPath_VSYS2, 63 VCC4, 64 SW4, 65 VFB4, 66 GND4, 67 BAT_TS1, 68 EXT_TS2, 69 GNDPAD

## PSW3_B_0
designator S?, comment PSW3_B  (value not drawn)
PARTS: 1; OriginalSymbolOrigin: (20,50); LEVEL: STD; DEVICE: BR-11C-11P6; Altium-Right: 30; Altium-Bottom: 40
pins: 1 P1, 2 P2, 3 P3

## PWC1X4_0
designator J?, comment PWC1X4  (value not drawn)
PARTS: 1; OriginalSymbolOrigin: (0,70); PKG_TYPE: 4; LEVEL: STD; DEVICE: HEAD1X4; Altium-Right: 40; Altium-Bottom: 70
pins: 1 A1, 2 A2, 3 A3, 4 A4, 5, 6

## R-0402
designator R?
Altium-Right: 20
pins: 1, 2

## R-0402_Dup1
designator R?
Altium-Right: 20
pins: 1, 2

## R-0603
designator R?
Altium-Right: 20
pins: 1, 2

## R-0805
designator R?
Altium-Right: 20
pins: 1, 2

## R-1206
designator R?
Altium-Right: 20
pins: 1, 2

## RESISTOR_0
designator R?
Altium-Right: 20; Altium-Bottom: 30
pins: 1, 2

## RESISTOR_1
designator R?
Altium-Right: 20; Altium-Bottom: 30
pins: 1, 2

## RF-IPEX-20279
designator IPEX?  Height: 1.25mm  Material: SCONN
SMD micro Coaxial Connector Receptacle vertial; Part_Name: MHF-20279; Altium-Right: 60
pins: 1 GND1, 2 SIG, 3 GND2, 4 GND3

## RK808_0
designator U?  (value not drawn)
Altium-Right: 220; Altium-Bottom: 630
pins: 1 VCC10 (power), 2 VLDO6 (power), 3 VLDO3 (power), 4 VCC7 (power), 5 VLDO7 (power), 6 ResetKey/VPPOTP (in), 7 VSWOUT1 (power), 8 VCC8 (power), 9 VCCRTC (power), 10 VCC12 (power), 11 VSWOUT2 (power), 12 VLDO4 (power), 13 VCC9 (power), 14 VLDO5 (power), 15 VLDO8 (power), 16 VCC11 (power), 17 VDDIO (power), 18 SDA (oc), 19 SCL (oc), 20 NRESPWRON (io), 21 DVS2 (in), 22 DVS1 (in), 23 VCC2 (power), 24 VCC2 (power), 25 SW2 (power), 26 SW2 (power), 27 GND2 (power), 28 GND2 (power), 29 VFB2 (in), 30 DGND (power), 31 VLDO1 (power), 32 VCC6 (power), 33 VLDO2 (power), 34 VDC (in), 35 VLDOA (power), 36 VCCA (power), 37 VREF (power), 38 AGND (power), 39 VFB1 (in), 40 GND1 (power), 41 GND1 (power), 42 SW1 (power), 43 SW1 (power), 44 VCC1 (power), 45 VCC1 (power), 46 GND5 (power), 47 NC (hiz), 48 NC (in), 49 INT (out), 50 SLEEP (in), 51 PWRON (in), 52 BOOT0 (in), 53 BOOT1 (in), 54 DVSOK (out), 55 EXT_EN (out), 56 VFB3 (in), 57 GND3 (power), 58 SW3 (power), 59 VCC3 (power), 60 VCC4 (power), 61 SW4 (power), 62 GND4 (power), 63 VFB4 (in), 64 VREFGND (power), 65 OSC32KIN (in), 66 OSC32KOUT (out), 67 CLK32KOUT2 (oc), 68 always on CLK32KOUT1 (oc), 69 GNDPAD (power)

## RK808_1
designator U?  (value not drawn)
Altium-Right: 220; Altium-Bottom: 630
pins: 1 VCC10 (power), 2 VLDO6 (power), 3 VLDO3 (power), 4 VCC7 (power), 5 VLDO7 (power), 6 ResetKey/VPPOTP (in), 7 VSWOUT1 (power), 8 VCC8 (power), 9 VCCRTC (power), 10 VCC12 (power), 11 VSWOUT2 (power), 12 VLDO4 (power), 13 VCC9 (power), 14 VLDO5 (power), 15 VLDO8 (power), 16 VCC11 (power), 17 VDDIO (power), 18 SDA (oc), 19 SCL (oc), 20 NRESPWRON (io), 21 DVS2 (in), 22 DVS1 (in), 23 VCC2 (power), 24 VCC2 (power), 25 SW2 (power), 26 SW2 (power), 27 GND2 (power), 28 GND2 (power), 29 VFB2 (in), 30 DGND (power), 31 VLDO1 (power), 32 VCC6 (power), 33 VLDO2 (power), 34 VDC (in), 35 VLDOA (power), 36 VCCA (power), 37 VREF (power), 38 AGND (power), 39 VFB1 (in), 40 GND1 (power), 41 GND1 (power), 42 SW1 (power), 43 SW1 (power), 44 VCC1 (power), 45 VCC1 (power), 46 GND5 (power), 47 NC (hiz), 48 NC (in), 49 INT, 50 SLEEP (in), 51 PWRON (in), 52 BOOT0 (in), 53 BOOT1 (in), 54 DVSOK (out), 55 EXT_EN (out), 56 VFB3 (in), 57 GND3 (power), 58 SW3 (power), 59 VCC3 (power), 60 VCC4 (power), 61 SW4 (power), 62 GND4 (power), 63 VFB4 (in), 64 VREFGND (power), 65 OSC32KIN (in), 66 OSC32KOUT (out), 67 CLK32KOUT2 (oc), 68 always on CLK32KOUT1 (oc), 69 GNDPAD (power)

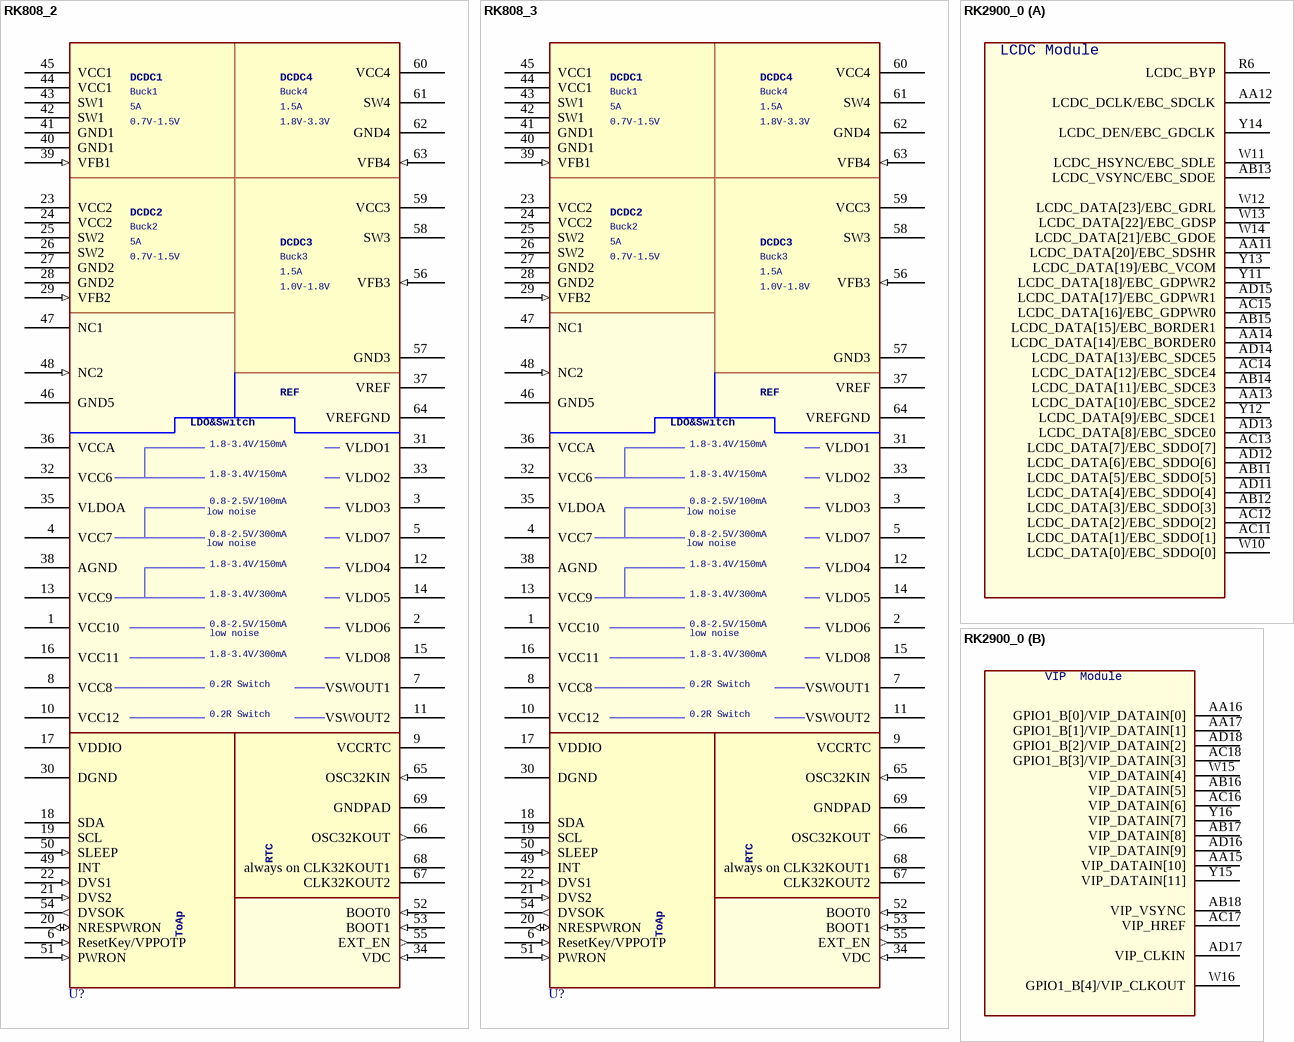
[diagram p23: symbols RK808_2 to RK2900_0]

## RK808_2
designator U?  (value not drawn)
Altium-Right: 220; Altium-Bottom: 630
pins: 1 VCC10 (power), 2 VLDO6 (power), 3 VLDO3 (power), 4 VCC7 (power), 5 VLDO7 (power), 6 ResetKey/VPPOTP (in), 7 VSWOUT1 (power), 8 VCC8 (power), 9 VCCRTC (power), 10 VCC12 (power), 11 VSWOUT2 (power), 12 VLDO4 (power), 13 VCC9 (power), 14 VLDO5 (power), 15 VLDO8 (power), 16 VCC11 (power), 17 VDDIO (power), 18 SDA (oc), 19 SCL (oc), 20 NRESPWRON (io), 21 DVS2 (in), 22 DVS1 (in), 23 VCC2 (power), 24 VCC2 (power), 25 SW2 (power), 26 SW2 (power), 27 GND2 (power), 28 GND2 (power), 29 VFB2 (in), 30 DGND (power), 31 VLDO1 (power), 32 VCC6 (power), 33 VLDO2 (power), 34 VDC (in), 35 VLDOA (power), 36 VCCA (power), 37 VREF (power), 38 AGND (power), 39 VFB1 (in), 40 GND1 (power), 41 GND1 (power), 42 SW1 (power), 43 SW1 (power), 44 VCC1 (power), 45 VCC1 (power), 46 GND5 (power), 47 NC1 (hiz), 48 NC2 (in), 49 INT, 50 SLEEP (in), 51 PWRON (in), 52 BOOT0 (in), 53 BOOT1 (in), 54 DVSOK (out), 55 EXT_EN (out), 56 VFB3 (in), 57 GND3 (power), 58 SW3 (power), 59 VCC3 (power), 60 VCC4 (power), 61 SW4 (power), 62 GND4 (power), 63 VFB4 (in), 64 VREFGND (power), 65 OSC32KIN (in), 66 OSC32KOUT (out), 67 CLK32KOUT2 (oc), 68 always on CLK32KOUT1 (oc), 69 GNDPAD (power)

## RK808_3
designator U?  (value not drawn)
Altium-Right: 220; Altium-Bottom: 630
pins: 1 VCC10 (power), 2 VLDO6 (power), 3 VLDO3 (power), 4 VCC7 (power), 5 VLDO7 (power), 6 ResetKey/VPPOTP (in), 7 VSWOUT1 (power), 8 VCC8 (power), 9 VCCRTC (power), 10 VCC12 (power), 11 VSWOUT2 (power), 12 VLDO4 (power), 13 VCC9 (power), 14 VLDO5 (power), 15 VLDO8 (power), 16 VCC11 (power), 17 VDDIO (power), 18 SDA (oc), 19 SCL (oc), 20 NRESPWRON (io), 21 DVS2 (in), 22 DVS1 (in), 23 VCC2 (power), 24 VCC2 (power), 25 SW2 (power), 26 SW2 (power), 27 GND2 (power), 28 GND2 (power), 29 VFB2 (in), 30 DGND (power), 31 VLDO1 (power), 32 VCC6 (power), 33 VLDO2 (power), 34 VDC (in), 35 VLDOA (power), 36 VCCA (power), 37 VREF (power), 38 AGND (power), 39 VFB1 (in), 40 GND1 (power), 41 GND1 (power), 42 SW1 (power), 43 SW1 (power), 44 VCC1 (power), 45 VCC1 (power), 46 GND5 (power), 47 NC1 (hiz), 48 NC2 (in), 49 INT, 50 SLEEP (in), 51 PWRON (in), 52 BOOT0 (in), 53 BOOT1 (in), 54 DVSOK (out), 55 EXT_EN (out), 56 VFB3 (in), 57 GND3 (power), 58 SW3 (power), 59 VCC3 (power), 60 VCC4 (power), 61 SW4 (power), 62 GND4 (power), 63 VFB4 (in), 64 VREFGND (power), 65 OSC32KIN (in), 66 OSC32KOUT (out), 67 CLK32KOUT2 (oc), 68 always on CLK32KOUT1 (oc), 69 GNDPAD (power)

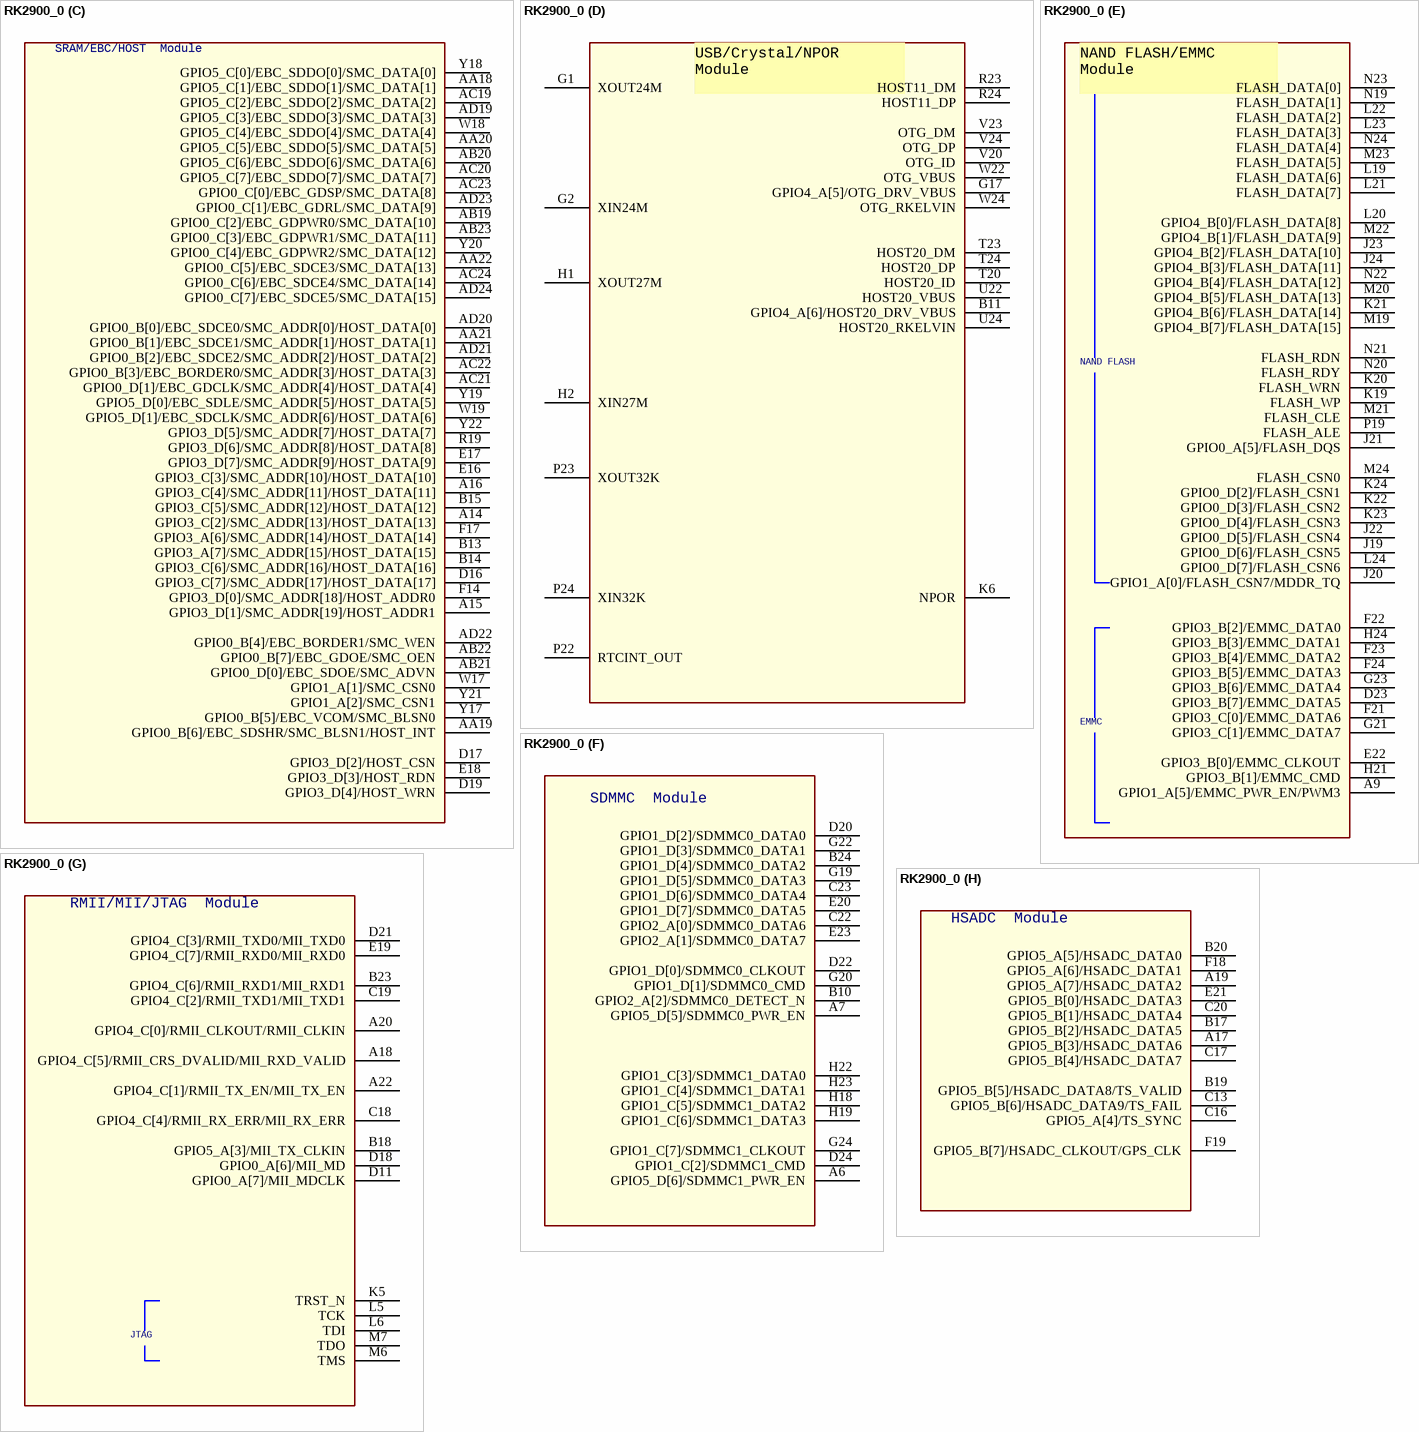
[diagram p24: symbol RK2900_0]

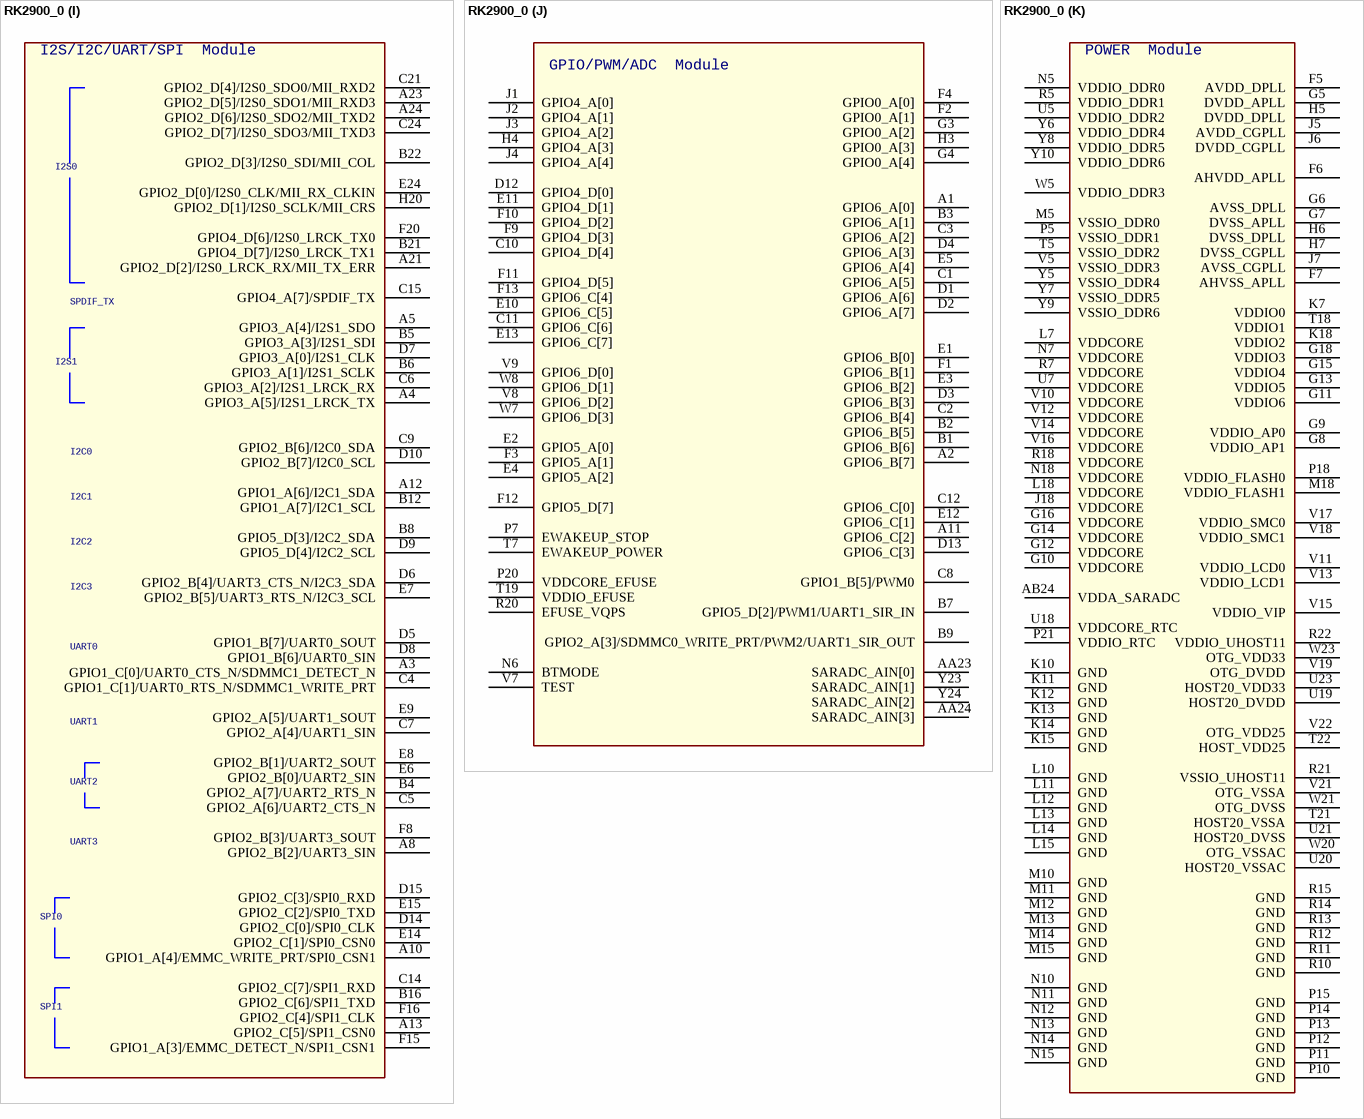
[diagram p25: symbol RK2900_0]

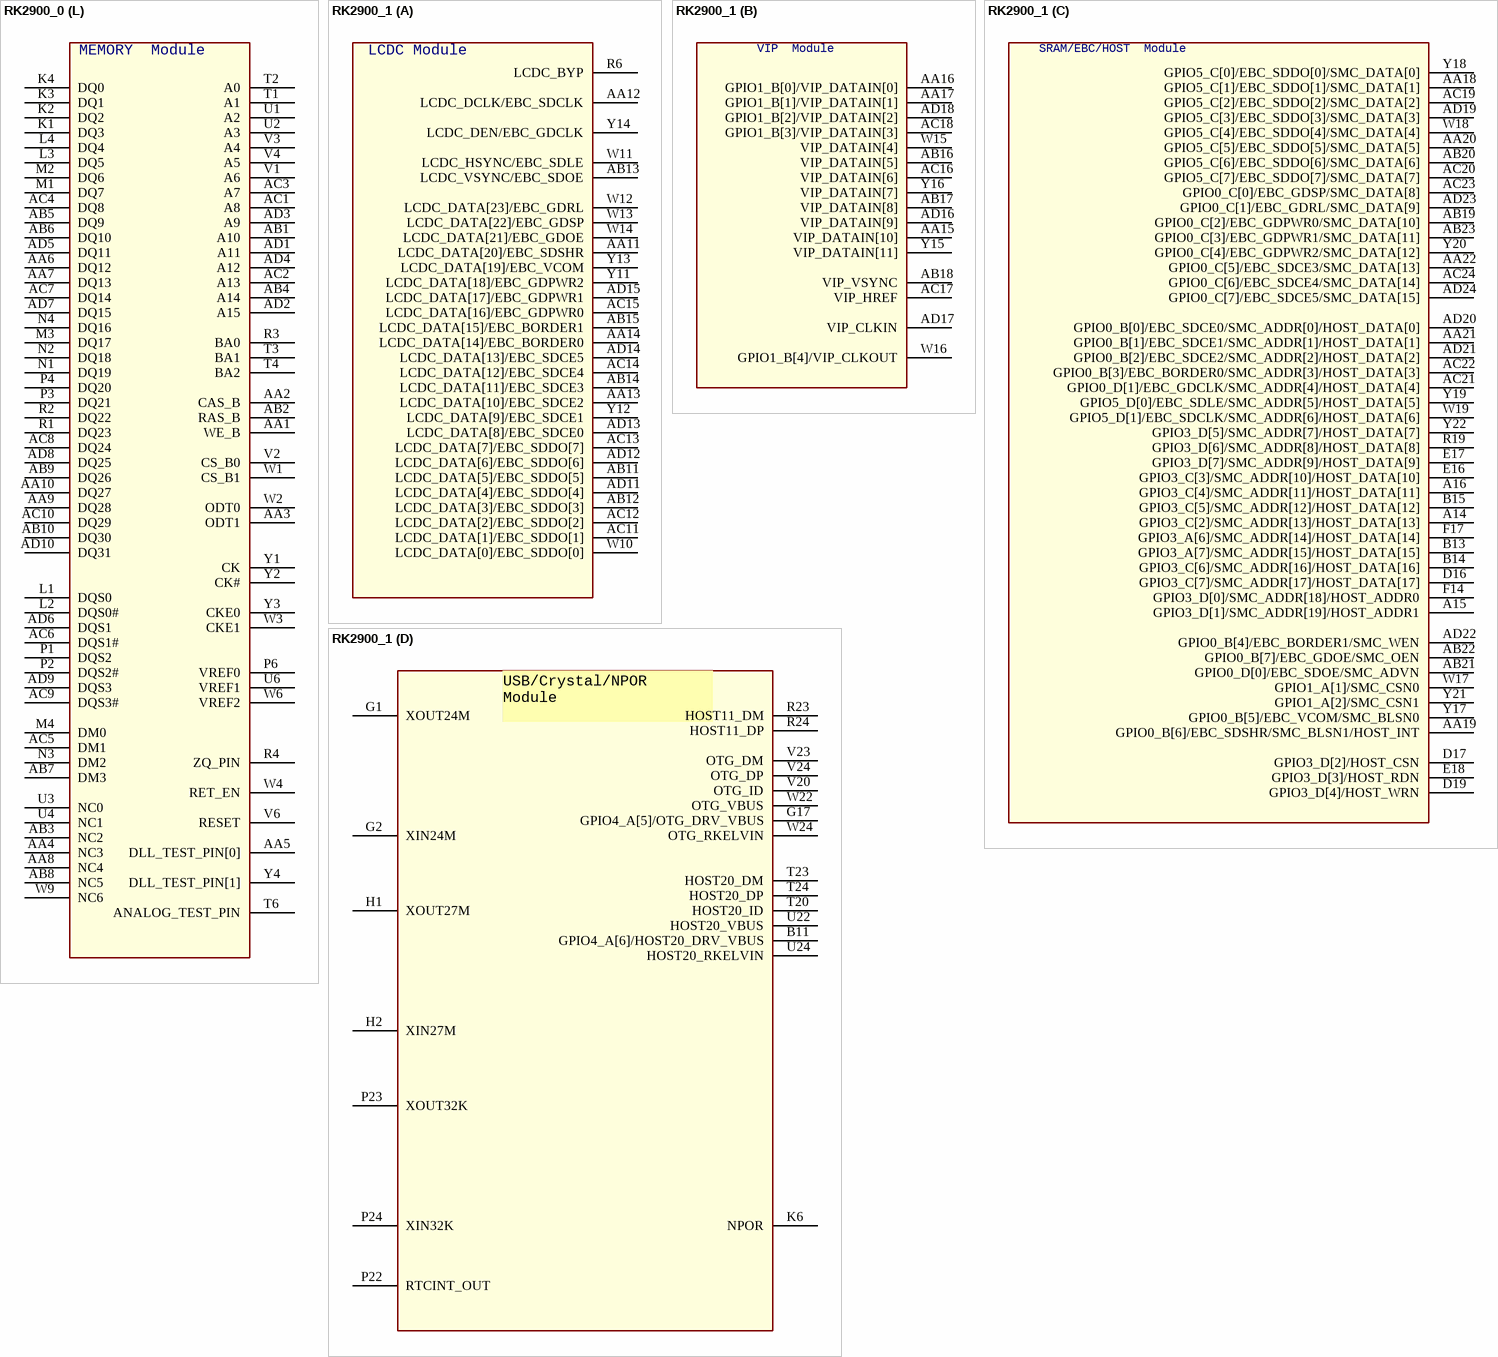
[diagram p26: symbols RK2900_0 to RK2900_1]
